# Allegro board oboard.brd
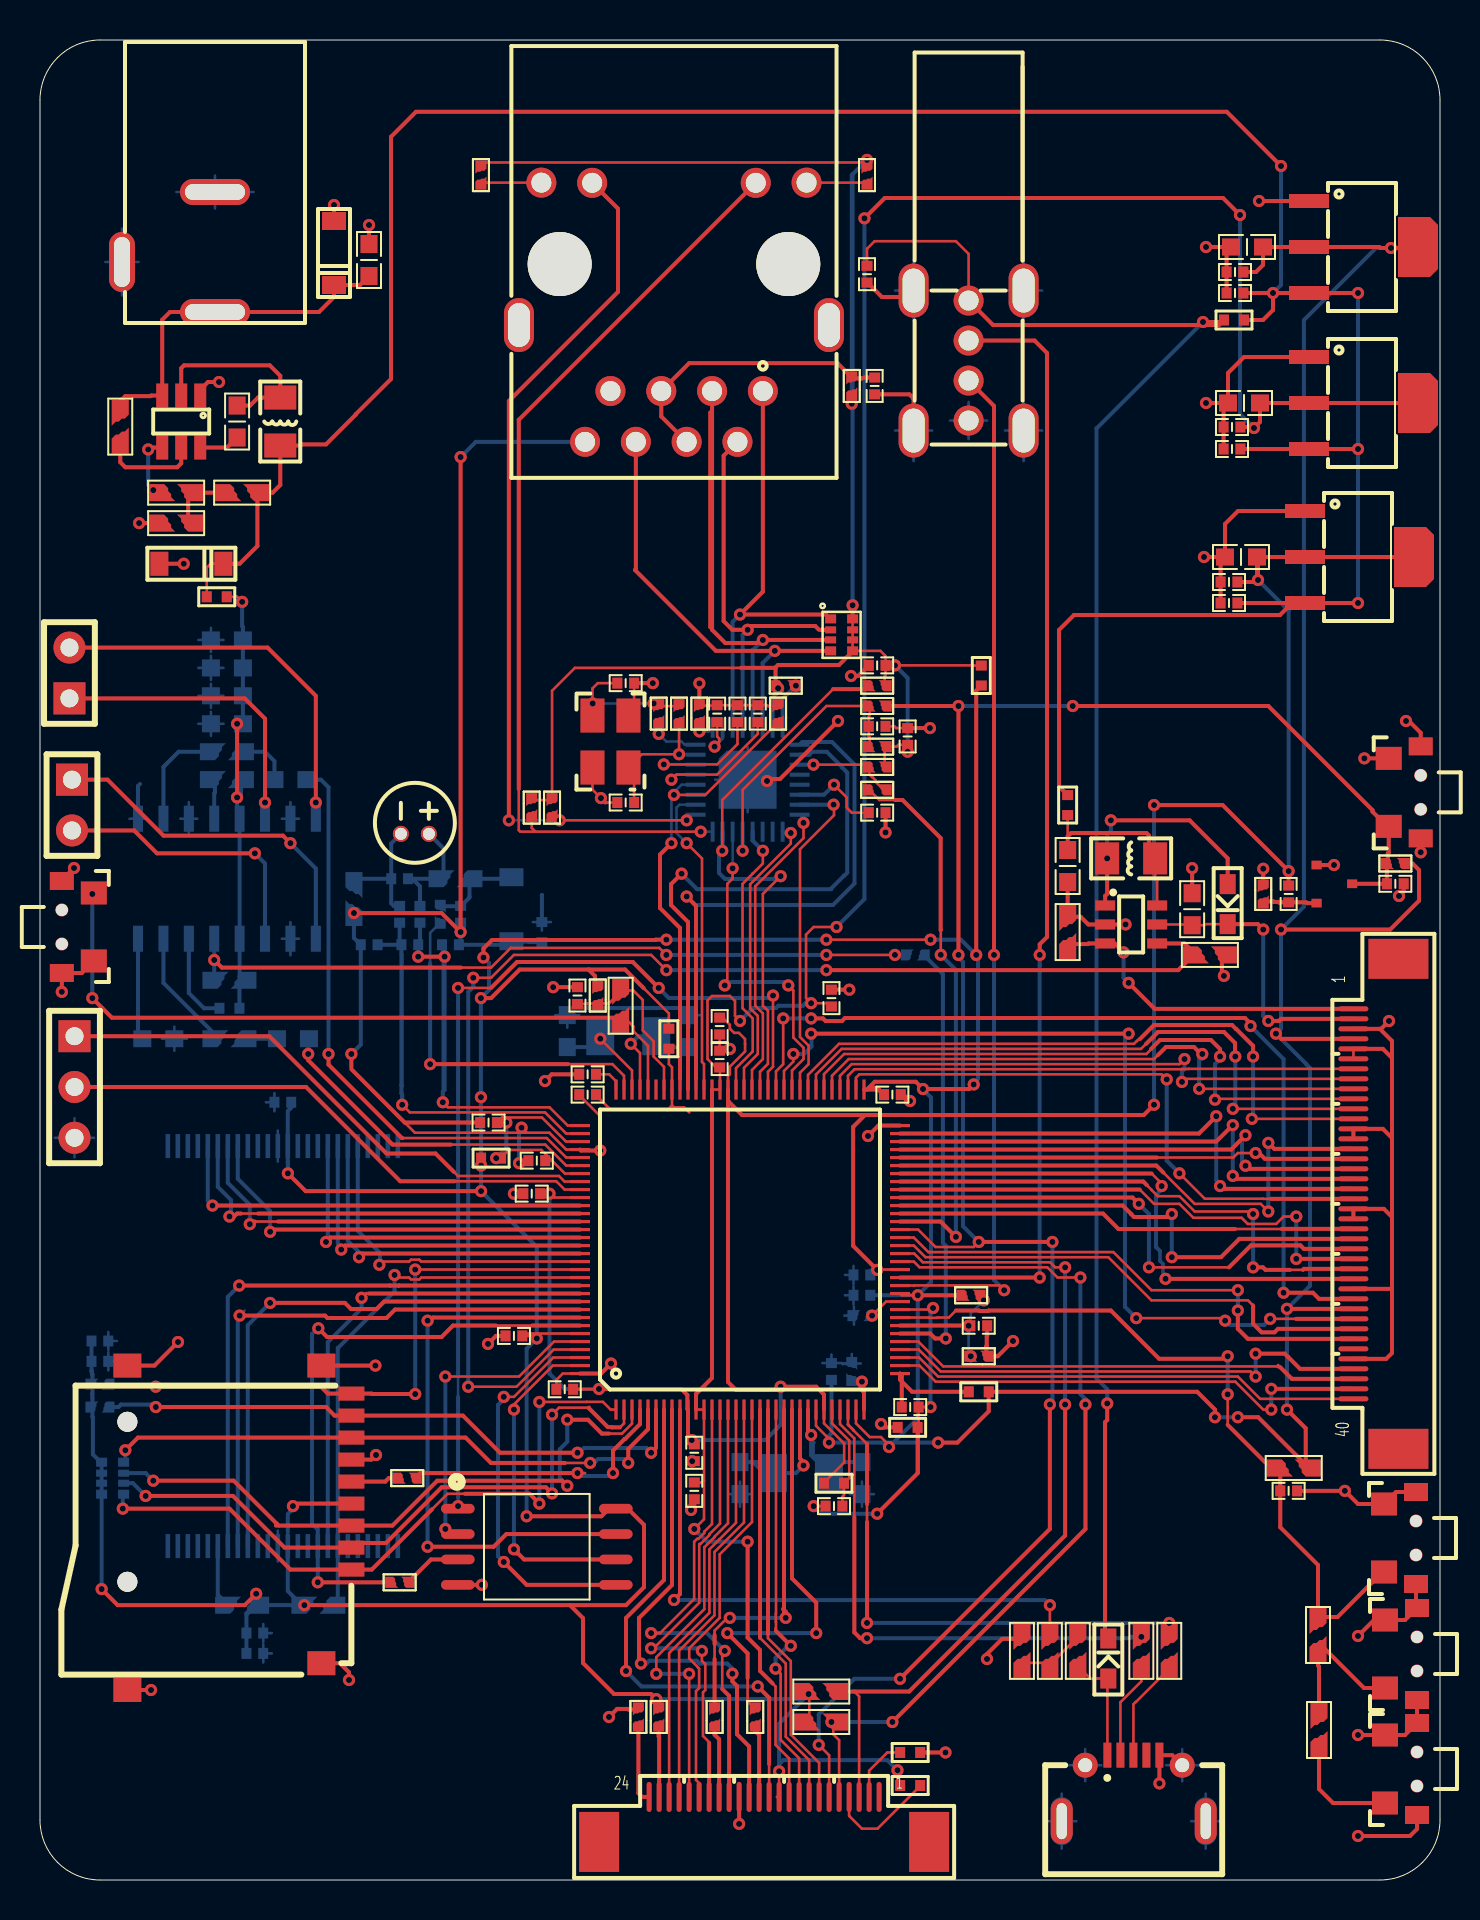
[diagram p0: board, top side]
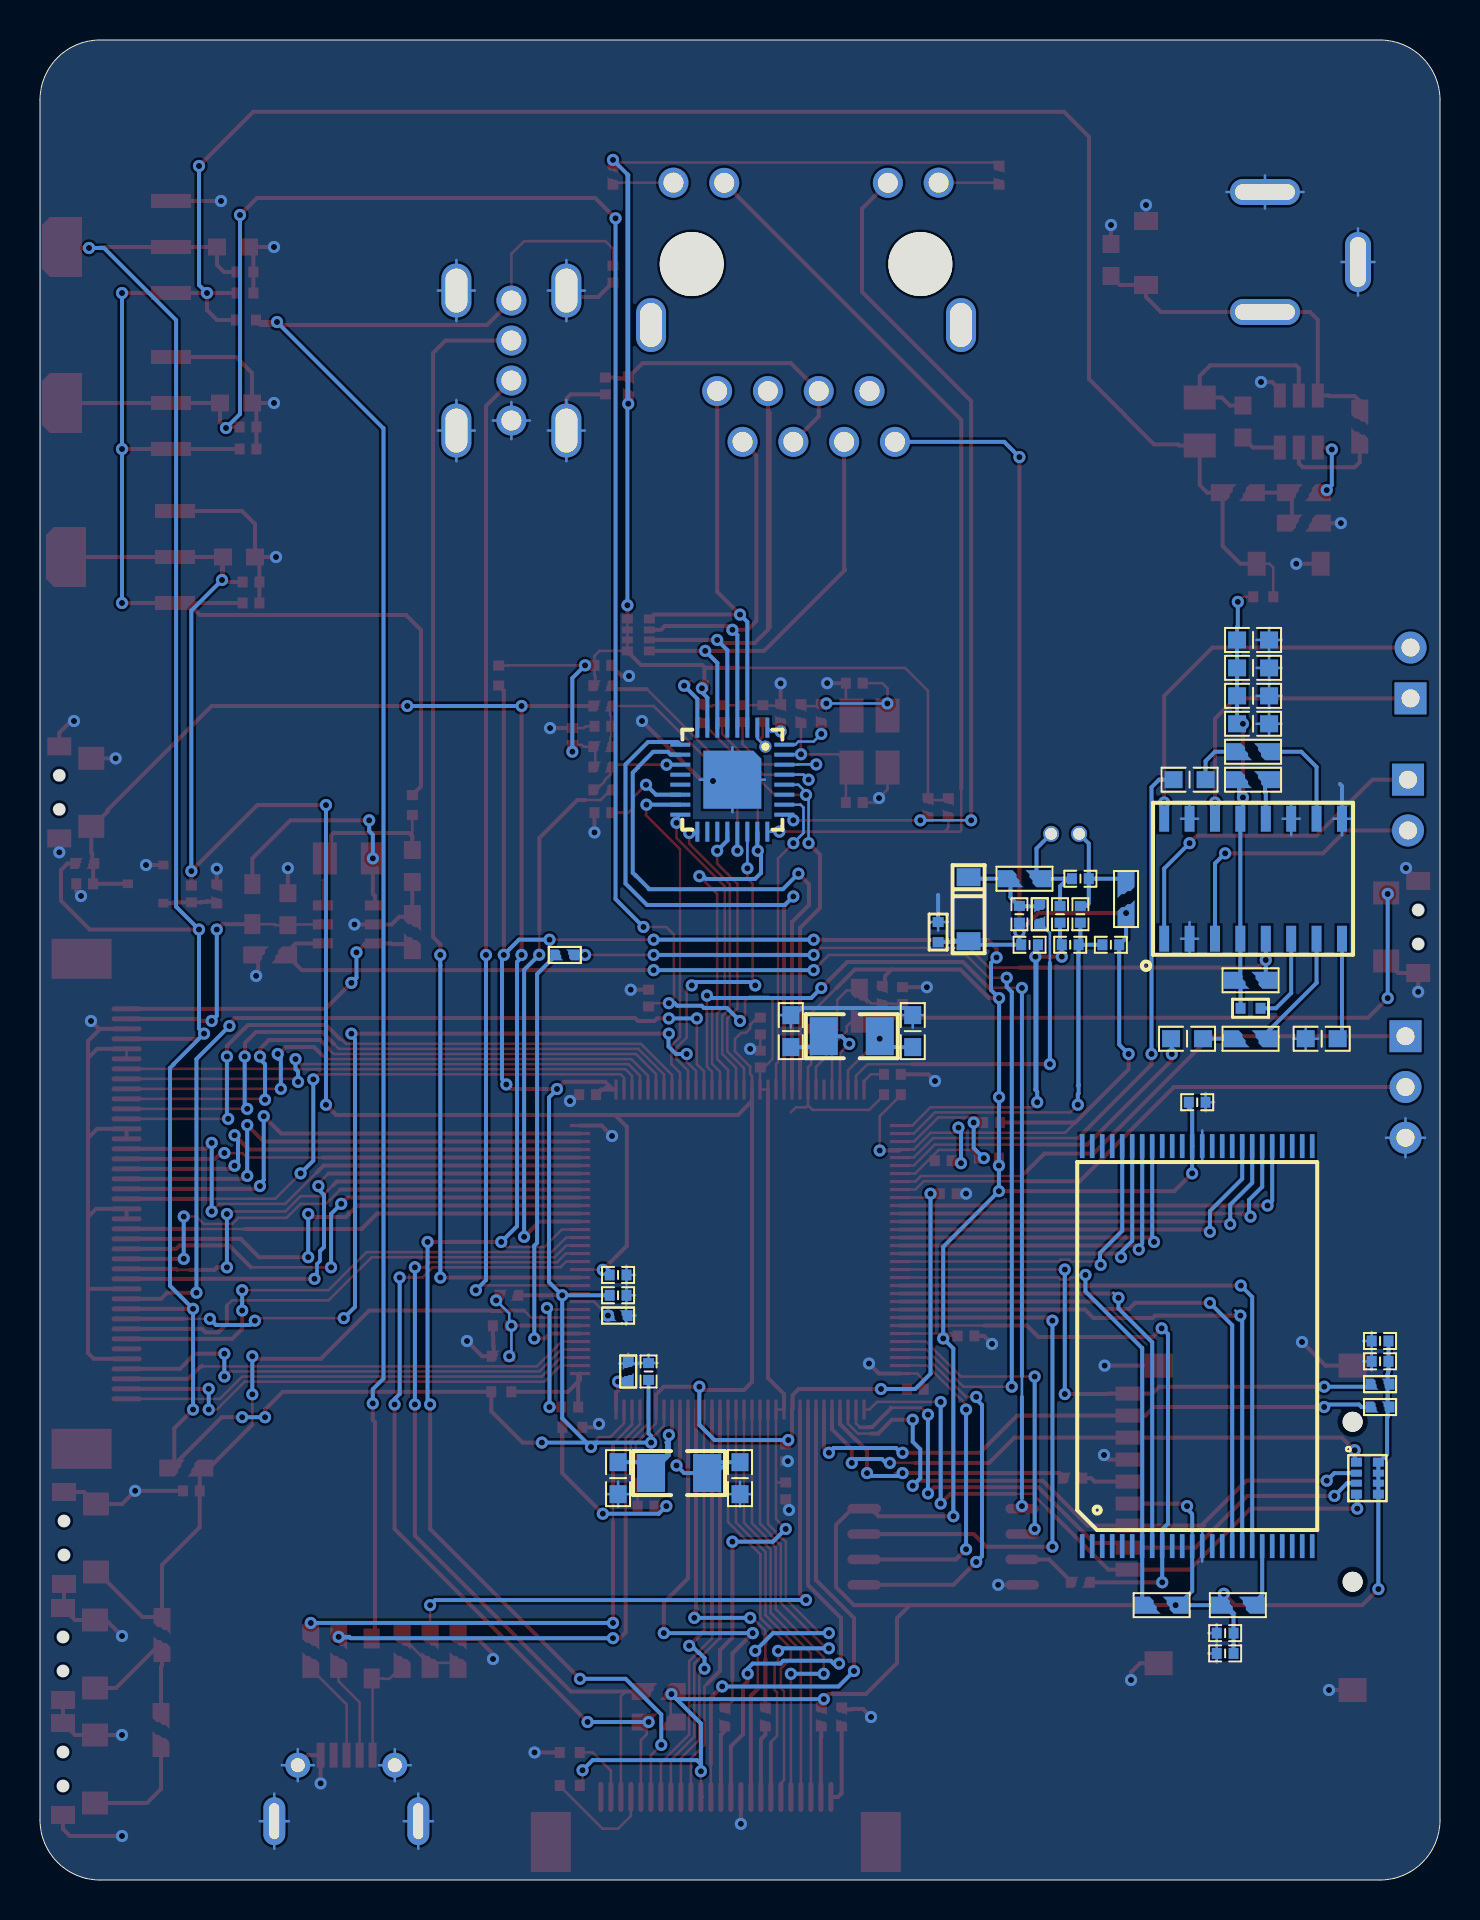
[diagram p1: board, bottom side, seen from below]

Outline 70 x 92 mm; copper layers: TOP, BOTTOM. Coordinates in mm from the lower left corner of the outline.
Outline path: 0,89 0,3 arc(0.88,0.88) 3,0 67,0 arc(69.12,0.88) 70,3 70,89 arc(69.12,91.12) 67,92 3,92 arc(0.88,91.12) 0,89

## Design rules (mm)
constraint set DEFAULT: min track width 0.127

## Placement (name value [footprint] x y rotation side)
C1  1uF  [CAP0402]  27.38 40.28 180 top
C2  15pF  [CAP0603]  32.46 42.44 90 bottom
C3  15pF  [CAP0603]  26.36 42.44 90 bottom
C4  15pF  [CAP0603]  41.1 20.09 270 bottom
C5  15pF  [CAP0603]  35 20.09 270 bottom
C6  0.1uF  [CAP0402]  46.94 27.71 0 top
C7  100nF  [CAP0402]  26.87 44.22 90 top
C8  100nF  [CAP0402]  33.98 42.7 270 top
C9  100nF  [CAP0402]  22.43 37.87 180 top
C10  100nF  [CAP0402]  41.1 29.24 180 bottom
C11  100nF  [CAP0402]  41.1 30.25 180 bottom
C12  0.1uF  [CAP0402]  62.43 49.3 270 top
C13  100nF  [CAP0402]  24.84 35.97 180 top
C14  100nF  [CAP0402]  42.62 39.27 0 top
C15  100nF  [CAP0402]  26.24 24.54 180 top
C16  0.1uF  [CAP0402]  67.77 49.81 0 top
C17  100nF  [CAP0402]  27.38 39.27 180 top
C18  100nF  [CAP0402]  10.74 11.33 0 bottom
C19  100nF  [CAP0402]  32.71 21.36 270 top
C20  100nF  [CAP0402]  43.51 23.65 0 top
C21  100nF  [CAP0402]  39.57 25.43 90 bottom
C22  100nF  [CAP0402]  24.59 34.32 180 top
C23  100nF  [CAP0402]  39.7 18.7 180 top
C24  100nF  [CAP0402]  23.7 27.2 180 top
C25  100nF  [CAP0402]  32.71 19.46 270 top
C26  100nF  [CAP0402]  33.98 41.05 90 top
C27  100nF  [CAP0402]  39.57 44.09 90 top
C29  0.01uF  [CAP0402]  10.74 12.34 0 bottom
C30  0.01uF  [CAP0402]  12.14 38.89 180 bottom
C31  0.01uF  [CAP0402]  3 26.95 180 bottom
C32  0.01uF  [CAP0402]  3 25.93 180 bottom
C33  1uF  [CAP0603]  51.38 50.7 270 top
C34  0.22uF  [CAP0603]  57.61 48.54 90 top
C35  10uF  [CAP0603]  9.35 60.61 180 bottom
C36  1uF  [CAP0603]  9.35 62 180 bottom
C37  10uF  [CAP0603]  9.35 57.81 180 bottom
C38  1uF  [CAP0603]  9.35 59.21 180 bottom
C39  104  [CAP0402]  62.43 19.46 0 top
C40  220nF  [CAP0603]  12.65 42.06 180 bottom
C41  220nF  [CAP0603]  12.52 55.02 0 bottom
C42  1uF  [CAP0603]  5.92 42.06 180 bottom
C43  2.2uF  [CAP3216]  23.57 48.54 270 bottom
C44  100nF  [CAP0402]  21.03 48.29 270 bottom
C45  2.2uF  [CAP0402]  19 48.29 270 bottom
C46  470pF  [CAP0402]  18.49 46.76 0 bottom
C47  330pF  [CAP0402]  17.98 50.06 0 bottom
C48  2.2uF  [CAP0402]  17.98 48.29 270 bottom
C49  330pF  [CAP0402]  20.52 46.76 0 bottom
C50  330pF  [CAP0402]  16.46 46.76 180 bottom
C51  100nF  [CAP0402]  43.38 57.18 90 top
C52  100nF  [CAP0402]  35.89 58.32 270 top
C53  100nF  [CAP0402]  34.87 58.32 90 top
C54  100nF  [CAP0402]  41.86 60.73 180 top
C55  100nF  [CAP0402]  33.86 58.32 270 top
C56  100nF  [CAP0402]  41.86 53.37 0 top
C57  100nF  [CAP0402]  41.73 74.7 270 top
C58  20pF  [CAP0402]  29.29 53.87 0 top
C59  100nF  [CAP0402]  41.86 57.68 0 top
C60  20pF  [CAP0402]  29.29 59.84 180 top
C61  100nF  [CAP0402]  59.75 79.35 180 top
C62  2.2uF  [CAP0603]  60.35 81.65 180 top
C63  100nF  [CAP0402]  59.75 80.4 180 top
C64  100nF  [CAP0402]  59.6 71.55 180 top
C65  2.2uF  [CAP0603]  60.2 73.85 180 top
C66  100nF  [CAP0402]  59.6 72.65 180 top
C67  100nF  [CAP0402]  59.45 63.85 180 top
C68  2.2uF  [CAP0603]  60.05 66.15 180 top
C69  100nF  [CAP0402]  59.45 64.9 180 top
C70  1uF  [CAP0603]  9.85 72.92 270 top
C71  22uF  [CAP3216]  7.57 65.81 180 top
C72  6V/22uF  [CAP3216]  14.7 81.35 90 top
C73  6V/0.1uF  [CAP0603]  16.45 81 90 top
C74  0.1uF  [CAP0402]  41.35 80.29 270 top
D1  1N4148  [1N4148-SOD323]  59.38 48.79 90 top
D2  1N4148  [1N4148-SOD323]  53.41 11.08 270 top
J1  -  [TF-SOCKET]  15.57 15.52 270 top
J2  LCD_RGB_40P  [FPC-40]  68.02 33.81 90 top
J3  OV2640_DVP_24P  [FPC-24]  32.21 1.8 0 top
J4  Speaker Left  [HEADER1X2_2_54]  1.6 55.02 0 top
J5  Speaker Right  [HEADER1X2_2_54]  1.47 59.08 180 top
J6  Debug  [HEADER1X3_2_54]  1.73 42.19 0 top
J8  RJ45  [RJ45_13F-64GYDP2NL]  31.7 71.91 180 top
J9  USB  [USB-AF]  46.43 75.97 0 top
J10  USB  [MICROUSB]  54.69 5.74 180 top
J11  DC 005 25A  [DC_005_25A]  8.75 91.9 270 top
L1  BLM15AG102  [BLM15AG221SN1D]  22.55 36.09 0 top
L2  BLM15AG102  [BLM15AG221SN1D]  31.44 42.06 270 top
L3  22uH  [MLF2012]  54.56 51.08 180 top
L4  10uH  [BLM15AG221SN1D]  9.47 43.59 180 bottom
L5  BLM15AG102  [BLM15AG221SN1D]  47.06 60.22 90 top
L6  4.7uH  [MLF2012]  12.01 72.92 270 top
L7  BLM15AG102  [BLM15AG221SN1D]  8.84 64.16 180 top
L8  BLM15AG102  [BLM15AG221SN1D]  46.94 24.41 0 top
L9  BLM15AG102  [BLM15AG221SN1D]  39.7 19.84 180 top
L10  BLM15AG102  [BLM15AG221SN1D]  25.09 47.4 90 bottom
L11  BLM15AG102  [BLM15AG221SN1D]  59.7 78 180 top
L12  BLM15AG102  [BLM15AG221SN1D]  51.38 53.75 270 top
L13  BLM15AG102  [BLM15AG221SN1D]  43.51 4.73 180 top
L14  BLM15AG102  [BLM15AG221SN1D]  43.51 6.38 0 top
L15  BLM15AG102  [BLM15AG221SN1D]  43.38 22.63 180 top
Q1  SS8050  [SOT23]  64.72 49.81 0 top
R1  12.1K 1%  [RES0402]  40.59 25.43 90 bottom
R2  12.1K 1%  [RES0402]  41.1 28.22 180 bottom
R3  0R  [RES0402]  27.89 44.22 270 top
R4  100K  [RES0603]  29.03 43.71 270 top
R5  1K/DNP  [RES0402]  46.56 29.24 0 top
R6  10K/DNP  [RES0402]  46.94 26.19 0 top
R7  100K  [RES0402]  67.77 50.83 0 top
R8  10K  [RES0402]  61.16 49.3 90 top
R9  100K  [RES0603]  13.92 13.74 0 bottom
R10  100K  [RES0603]  10.11 13.74 180 bottom
R11  0R  [RES0402]  17.98 14.89 0 top
R12  100K  [RES0402]  3 23.65 180 bottom
R13  100K  [RES0402]  3 24.79 180 bottom
R14  22R  [RES0402]  18.36 20.09 180 top
R15  22R  [RES0402]  35.76 8.15 270 top
R16  22R  [RES0402]  33.73 8.15 270 top
R17  0R/DNP  [RES0402]  30.94 8.15 270 top
R18  0R/DNP  [RES0402]  29.92 8.15 270 top
R19  10K  [RES0603]  39.06 7.9 0 top
R20  10K  [RES0603]  39.06 9.42 0 top
R21  5R1  [RES0603]  51.38 47.4 90 top
R22  100K  [RES0603]  58.5 46.25 0 top
R23  100K  [RES0603]  62.69 20.6 0 top
R24  10K  [RES0603]  9.35 55.02 0 bottom
R25  10K  [RES0603]  63.9 12.25 270 top
R26  10K  [RES0603]  63.95 7.5 270 top
R28  10K  [RES0603]  9.47 42.06 180 bottom
R29  10K  [RES0603]  9.35 56.41 0 bottom
R30  10K  [RES0603]  9.47 44.98 180 bottom
R31  0R  [RES0402]  43.76 46.25 180 bottom
R32  0R  [RES0402]  20.01 48.29 90 bottom
R33  1.5K  [RES0603]  20.78 50.06 180 bottom
R34  5.1K  [RES0603]  15.7 49.05 90 bottom
R35  0R  [RES0402]  40.59 74.7 270 top
R36  0R  [RES0402]  41.86 54.51 0 top
R37  0R  [RES0402]  41.86 58.7 180 top
R38  10K  [RES0402]  41.86 56.67 180 top
R39  0R  [RES0402]  32.97 58.32 270 top
R40  1M  [RES0402]  31.95 58.32 90 top
R41  0R  [RES0402]  30.94 58.32 90 top
R42  4.7K  [RES0402]  37.29 59.72 180 top
R43  4.7K  [RES0402]  41.86 55.65 0 top
R44  4.7K  [RES0402]  41.86 59.72 0 top
R45  4.7K  [RES0402]  25.6 53.62 90 top
R46  330R  [RES0402]  22.05 85.24 90 top
R47  4.7K  [RES0402]  24.59 53.62 90 top
R48  330R  [RES0402]  41.35 85.24 90 top
R49  4.7K  [RES0402]  36.91 58.32 270 top
R50  100K  [RES0603]  4.01 72.67 270 top
R51  40.2K  [RES0603]  10.11 69.37 180 top
R52  75K  [RES0603]  6.81 69.37 0 top
R53  13K  [RES0603]  6.81 67.84 0 top
R54  22R  [RES0603]  55.07 11.46 90 top
R55  22R  [RES0603]  56.46 11.46 90 top
R56  10K  [RES0603]  50.49 11.46 90 top
R57  10K  [RES0603]  51.89 11.46 90 top
R58  22K  [RES0603]  49.1 11.46 90 top
RN1  10K 0402 RESAR  [RN4D02_0402]  3.63 20.09 270 bottom
RN2  49.9R 0402 RESAR  [RN4D02_0402]  40.08 62.26 270 top
SW1  TS_018-4.55x3.5x1.8  [TS_018-4P55X3P5X1P8]  1.09 47.65 180 top
SW2  TS_018-4.55x3.5x1.8  [TS_018-4P55X3P5X1P8]  69.04 54.38 0 top
SW3  TS_018-4.55x3.5x1.8  [TS_018-4P55X3P5X1P8]  68.8 17.1 0 top
SW4  TS_018-4.55x3.5x1.8  [TS_018-4P55X3P5X1P8]  68.85 11.3 0 top
SW5  TS_018-4.55x3.5x1.8  [TS_018-4P55X3P5X1P8]  68.85 5.55 0 top
U1  N3292xUxDN  [N3292XUXDN-LQFP128]  35 31.52 90 top
U2  W29N01  [W290XHVSINA-TSOP48]  12.14 26.7 90 bottom
U3  W25QXX  [W25QXX_SOP8_208MIL]  24.84 16.66 0 top
U4  PT4101  [PT4101-SOT23-6]  54.56 47.78 0 top
U5  PAM8403  [PAM8403-SOP16]  9.35 50.06 90 bottom
U6  MIC  [GMI4015-MIC]  18.74 52.86 270 top
U7  RT8201F-QFN32  [RTL8201-QFN32]  35.38 55.02 270 bottom
U8  AMS1117-SOT223-3-3V3  [AMS1117-SOT223-3]  66.1 81.65 270 top
U9  AMS1117-SOT223-3-1V8  [AMS1117-SOT223-3]  66.1 73.85 270 top
U10  AMS1117-SOT223-3-1V2  [AMS1117-SOT223-3]  65.9 66.15 270 top
U11  MP1470  [MP1470-TSOT23-6]  7.06 72.92 180 top
Y1  32768Hz  [CRYSTAL-3215]  29.41 42.19 180 bottom
Y2  12MHz  [CRYSTAL-3215]  38.05 20.35 180 bottom
Y3  25MHz  [YSX321SL-3_2X2_5X0_8]  28.52 56.92 90 top

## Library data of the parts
C1-C27 C29-C32 C51-C57 C59 C61 C63 C64 C66 C67 C69 C74 = CAP NP
C33-C42 C44 C46 C47 C49 C50 C58 C60 C70-C73 = CAPACITOR NON-POL
C43 C45 C48 C62 C65 C68 = CAP POL
D1 D2 = DIODE
J1 = TF-SOCKET
J2 = LCD_RGB_40P
J3 = OV2640_DVP_24P
J4 J5 = HEADER 2
J6 = HEADER 3
J8 = RJ45
J9 = USB AF
J10 = MICROUSB
J11 = DC005-25A
L1 L2 L5 L7-L15 = INDUCTOR
L3 L4 L6 = INDUCTOR/SM
Q1 = BPW37/TO
R1-R20 R35-R39 R54-R58 = RESISTOR
R21-R26 R28-R34 R40-R53 = RESISTOR/SM
RN1 RN2 = RESAR_IS_4/SM
SW1-SW5 = TS_018-4.55x3.5x1.8
U1 = N3292xUxDN
U2 = W29N01 GVSCAA
U3 = W25QXX
U4 = PT4101
U5 = PAM8403
U6 = MIC
U7 = RT8201F-QFN32
U8-U10 = ASM1117-SOT223-3
U11 = MP1470
Y1 Y2 = CRYSTAL
Y3 = YSX321SL

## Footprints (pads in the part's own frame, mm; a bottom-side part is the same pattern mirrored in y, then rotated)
1N4148-SOD323
  custom 0.2x0.2 smd: 1(-1,0) 2(1,0)
AMS1117-SOT223-3
  custom 0.175x0.175 smd: 1(-2.3,-2.65) 2(0,-2.65) 3(2.3,-2.65)
  custom 0.5x0.5 smd: 4(0,2.8)
BLM15AG221SN1D
  custom 0.125x0.125 smd: 1(-0.5,0) 2(0.5,0)
CAP0402
  custom 0.125x0.125 smd: 1(-0.42,0) 2(0.42,0)
CAP0603
  custom 0.212x0.212 smd: 1(-0.8,0) 2(0.8,0)
CAP3216
  custom 0.225x0.225 smd: 1(-1.6,0) 2(1.6,0)
CRYSTAL-3215
  custom 0.35x0.35 smd: 1(-1.4,0) 2(1.4,0)
DC_005_25A
  oval 1.3x3.5 hole 0.8x3: 1(13.5,0) 2(7.5,0)
  oval 3x1.3 hole 2.5x0.8: 3(11,-4.65)
FPC-24
  rect 2x3 smd: (-4.25,0.1) (12.25,0.1)
  oval 0.25x1.5 smd: 1(9.75,2.35) 2(9.25,2.35) 3(8.75,2.35) 4(8.25,2.35) 5(7.75,2.35) 6(7.25,2.35) 7(6.75,2.35) 8(6.25,2.35) 9(5.75,2.35) 10(5.25,2.35) 11(4.75,2.35) 12(4.25,2.35) 13(3.75,2.35) 14(3.25,2.35) 15(2.75,2.35) 16(2.25,2.35) 17(1.75,2.35) 18(1.25,2.35) 19(0.75,2.35) 20(0.25,2.35) 21(-0.25,2.35) 22(-0.75,2.35) 23(-1.25,2.35) 24(-1.75,2.35)
FPC-40
  rect 2x3 smd: (-12.25,0.1) (12.25,0.1)
  oval 0.25x1.5 smd: 1(9.75,2.35) 2(9.25,2.35) 3(8.75,2.35) 4(8.25,2.35) 5(7.75,2.35) 6(7.25,2.35) 7(6.75,2.35) 8(6.25,2.35) 9(5.75,2.35) 10(5.25,2.35) 11(4.75,2.35) 12(4.25,2.35) 13(3.75,2.35) 14(3.25,2.35) 15(2.75,2.35) 16(2.25,2.35) 17(1.75,2.35) 18(1.25,2.35) 19(0.75,2.35) 20(0.25,2.35) 21(-0.25,2.35) 22(-0.75,2.35) 23(-1.25,2.35) 24(-1.75,2.35) 25(-2.25,2.35) 26(-2.75,2.35) 27(-3.25,2.35) 28(-3.75,2.35) 29(-4.25,2.35) 30(-4.75,2.35) 31(-5.25,2.35) 32(-5.75,2.35) 33(-6.25,2.35) 34(-6.75,2.35) 35(-7.25,2.35) 36(-7.75,2.35) 37(-8.25,2.35) 38(-8.75,2.35) 39(-9.25,2.35) 40(-9.75,2.35)
GMI4015-MIC
  round 0.8 hole 0.6: 1(0.55,0.7) 2(0.55,-0.7)
HEADER1X2_2_54
  rect 1.6x1.6 hole 0.9: 1(0,0)
  round 1.6 hole 0.9: 2(0,-2.54)
HEADER1X3_2_54
  rect 1.6x1.6 hole 0.9: 1(0,0)
  round 1.6 hole 0.9: 2(0,-2.54) 3(0,-5.08)
MICROUSB
  rect 0.4x1.25 smd: 1(1.315,-0.5) 2(0.665,-0.5) 3(0.015,-0.5) 4(-0.635,-0.5) 5(-1.285,-0.5)
  round 1.25 hole 0.7: 6(-2.425,0) 7(2.425,0)
  oval 1.1x2.3 hole 0.5x1.8: 8(-3.6,2.8) 9(3.6,2.8)
MLF2012
  custom 0.3x0.3 smd: 1(-1.2,0) 2(1.2,0)
MP1470-TSOT23-6
  custom 0.15x0.15 smd: 1(-0.95,-1.3) 2(0,-1.3) 3(0.95,-1.3) 4(0.95,1.3) 5(0,1.3) 6(-0.95,1.3)
N3292XUXDN-LQFP128
  custom 0.04x0.04 smd: 1(-8,6.2) 2(-8,5.8) 3(-8,5.4) 4(-8,5) 5(-8,4.6) 6(-8,4.2) 7(-8,3.8) 8(-8,3.4) 9(-8,3) 10(-8,2.6) 11(-8,2.2) 12(-8,1.8) 13(-8,1.4) 14(-8,1) 15(-8,0.6) 16(-8,0.2) 17(-8,-0.2) 18(-8,-0.6) 19(-8,-1) 20(-8,-1.4) 21(-8,-1.8) 22(-8,-2.2) 23(-8,-2.6) 24(-8,-3) 25(-8,-3.4) 26(-8,-3.8) 27(-8,-4.2) 28(-8,-4.6) 29(-8,-5) 30(-8,-5.4) 31(-8,-5.8) 32(-8,-6.2) 33(-6.2,-8) 34(-5.8,-8) 35(-5.4,-8) 36(-5,-8) 37(-4.6,-8) 38(-4.2,-8) 39(-3.8,-8) 40(-3.4,-8) 41(-3,-8) 42(-2.6,-8) 43(-2.2,-8) 44(-1.8,-8) 45(-1.4,-8) 46(-1,-8) 47(-0.6,-8) 48(-0.2,-8) 49(0.2,-8) 50(0.6,-8) 51(1,-8) 52(1.4,-8) 53(1.8,-8) 54(2.2,-8) 55(2.6,-8) 56(3,-8) 57(3.4,-8) 58(3.8,-8) 59(4.2,-8) 60(4.6,-8) 61(5,-8) 62(5.4,-8) 63(5.8,-8) 64(6.2,-8) 65(8,-6.2) 66(8,-5.8) 67(8,-5.4) 68(8,-5) 69(8,-4.6) 70(8,-4.2) 71(8,-3.8) 72(8,-3.4) 73(8,-3) 74(8,-2.6) 75(8,-2.2) 76(8,-1.8) 77(8,-1.4) 78(8,-1) 79(8,-0.6) 80(8,-0.2) 81(8,0.2) 82(8,0.6) 83(8,1) 84(8,1.4) 85(8,1.8) 86(8,2.2) 87(8,2.6) 88(8,3) 89(8,3.4) 90(8,3.8) 91(8,4.2) 92(8,4.6) 93(8,5) 94(8,5.4) 95(8,5.8) 96(8,6.2) 97(6.2,8) 98(5.8,8) 99(5.4,8) 100(5,8) 101(4.6,8) 102(4.2,8) 103(3.8,8) 104(3.4,8) 105(3,8) 106(2.6,8) 107(2.2,8) 108(1.8,8) 109(1.4,8) 110(1,8) 111(0.6,8) 112(0.2,8) 113(-0.2,8) 114(-0.6,8) 115(-1,8) 116(-1.4,8) 117(-1.8,8) 118(-2.2,8) 119(-2.6,8) 120(-3,8) 121(-3.4,8) 122(-3.8,8) 123(-4.2,8) 124(-4.6,8) 125(-5,8) 126(-5.4,8) 127(-5.8,8) 128(-6.2,8)
PAM8403-SOP16
  custom 0.125x0.125 smd: 1(-3,4.445) 2(-3,3.175) 3(-3,1.905) 4(-3,0.635) 5(-3,-0.635) 6(-3,-1.905) 7(-3,-3.175) 8(-3,-4.445) 9(3,-4.445) 10(3,-3.175) 11(3,-1.905) 12(3,-0.635) 13(3,0.635) 14(3,1.905) 15(3,3.175) 16(3,4.445)
PT4101-SOT23-6
  custom 0.125x0.125 smd: 1(-1.3,0.95) 2(-1.3,0) 3(-1.3,-0.95) 4(1.3,-0.95) 5(1.3,0) 6(1.3,0.95)
RES0402
  custom 0.138x0.138 smd: 1(-0.4,0) 2(0.4,0)
RES0603
  custom 0.212x0.212 smd: 1(-0.7,0) 2(0.7,0)
RJ45_13F-64GYDP2NL
  round 1.5 hole 1: 1(-4.445,-2.54) 2(-3.175,0) 3(-1.905,-2.54) 4(-0.635,0) 5(0.635,-2.54) 6(1.905,0) 7(3.175,-2.54) 8(4.445,0) 9(-6.63,-12.96) 10(-4.09,-12.95) 11(4.09,-12.95) 12(6.63,-12.96)
  round 3.201 hole 3.2: M1(-5.715,-8.89) M2(5.715,-8.89)
  oval 1.5x2.7 hole 1.1x2.2: M3(-7.75,-5.84) M4(7.75,-5.84)
RN4D02_0402
  rect 0.45x0.55 smd: 1(-0.8,-0.55) 4(0.8,-0.55) 5(0.8,0.55) 8(-0.8,0.55)
  rect 0.35x0.55 smd: 2(-0.25,-0.55) 3(0.25,-0.55) 6(0.25,0.55) 7(-0.25,0.55)
RTL8201-QFN32
  custom 0.05x0.05 smd: 1(-2.6,1.75) 2(-2.6,1.25) 3(-2.6,0.75) 4(-2.6,0.25) 5(-2.6,-0.25) 6(-2.6,-0.75) 7(-2.6,-1.25) 8(-2.6,-1.75) 9(-1.75,-2.6) 10(-1.25,-2.6) 11(-0.75,-2.6) 12(-0.25,-2.6) 13(0.25,-2.6) 14(0.75,-2.6) 15(1.25,-2.6) 16(1.75,-2.6) 17(2.6,-1.75) 18(2.6,-1.25) 19(2.6,-0.75) 20(2.6,-0.25) 21(2.6,0.25) 22(2.6,0.75) 23(2.6,1.25) 24(2.6,1.75) 25(1.75,2.6) 26(1.25,2.6) 27(0.75,2.6) 28(0.25,2.6) 29(-0.25,2.6) 30(-0.75,2.6) 31(-1.25,2.6) 32(-1.75,2.6)
  custom 0.725x0.725 smd: 33(0,0)
SOT23
  rect 0.508x0.432 smd: 1(-0.889,0.94) 2(-0.889,-0.965) 3(0.889,0)
TF-SOCKET
  round 1 hole 1.1 unplated: (-7.39,-11.2) (0.61,-11.2)
  rect 0.7x1.3 smd: 1(0,0) 2(-1.1,0) 3(-2.2,0) 4(-3.3,0) 5(-4.4,0) 6(-5.5,0) 7(-6.6,0) 8(-7.7,0) 9(-8.8,0)
  rect 1.2x1.4 smd: 10(-10.2,-1.5) 11(4.68,-1.5) 12(-10.2,-11.2) 13(6.02,-11.2)
TS_018-4P55X3P5X1P8
  round 0.65 hole 0.6: (0,0.85) (0,-0.85)
  custom 0.225x0.225 smd: 1(0,2.3) 2(0,-2.3)
  custom 0.287x0.287 smd: 3(-1.6,1.7) 4(-1.6,-1.7)
USB-AF
  round 1.5 hole 1: 1(0,3) 2(0,1) 3(0,-1) 4(0,-3)
  oval 1.5x2.7 hole 1.1x2.2: 5(-2.75,3.5) 6(2.75,3.5) 7(-2.75,-3.5) 8(2.75,-3.5)
W25QXX_SOP8_208MIL
  custom 0.12x0.12 smd: 1(-3.95,1.905) 2(-3.95,0.635) 3(-3.95,-0.635) 4(-3.95,-1.905) 5(3.95,-1.905) 6(3.95,-0.635) 7(3.95,0.635) 8(3.95,1.905)
W290XHVSINA-TSOP48
  custom 0.058x0.058 smd: 1(-10,5.75) 2(-10,5.25) 3(-10,4.75) 4(-10,4.25) 5(-10,3.75) 6(-10,3.25) 7(-10,2.75) 8(-10,2.25) 9(-10,1.75) 10(-10,1.25) 11(-10,0.75) 12(-10,0.25) 13(-10,-0.25) 14(-10,-0.75) 15(-10,-1.25) 16(-10,-1.75) 17(-10,-2.25) 18(-10,-2.75) 19(-10,-3.25) 20(-10,-3.75) 21(-10,-4.25) 22(-10,-4.75) 23(-10,-5.25) 24(-10,-5.75) 25(10,-5.75) 26(10,-5.25) 27(10,-4.75) 28(10,-4.25) 29(10,-3.75) 30(10,-3.25) 31(10,-2.75) 32(10,-2.25) 33(10,-1.75) 34(10,-1.25) 35(10,-0.75) 36(10,-0.25) 37(10,0.25) 38(10,0.75) 39(10,1.25) 40(10,1.75) 41(10,2.25) 42(10,2.75) 43(10,3.25) 44(10,3.75) 45(10,4.25) 46(10,4.75) 47(10,5.25) 48(10,5.75)
YSX321SL-3_2X2_5X0_8
  custom 0.3x0.3 smd: 1(-1.3,-0.9) 2(1.3,-0.9) 3(1.3,0.9) 4(-1.3,0.9)

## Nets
AVDD1V2: C23.1 L9.1 U1.28
AVDD3V3: C20.1 L8.1 U1.33
AVDD3V3_AUDIO: C9.1 C13.1 L1.2 U1.99 U1.103
AVDD3V3_TV: C17.1 L2.2 U1.89
AVDD5V: C35.1 C36.1 C37.1 C38.1 L4.1 L7.1 R24.2 R30.1 U5.4 U5.13
DVDD1V2: C8.1 C11.1 C12.1 C15.1 C19.1 C22.1 C68.1 C69.1 L9.2 U1.10 U1.27 U1.46 U1.82 U1.106 U10.2 U10.4(VOUT)
DVDD1V8: C25.1 C26.1 C27.1 C65.1 C66.1 J3.10 U1.11 U1.12 U1.83 U1.84 U9.2 U9.4(VOUT)
DVDD5V: C61.1 C64.1 C67.1 C71.1 L6.2 L7.2 L11.1 L12.1 R51.1 U8.3 U9.3 U10.3
DVDD33: C10.1 C14.1 C18.1 C21.1 C24.1 C29.1 C30.1 C31.2 C32.2 C62.1 C63.1 J1.4(VDD) J2.4 J2.31 J3.11 L1.1 L2.1 L5.1 L8.2 L13.2 R3.1 R5.1 R7.2 R9.1 R10.1 R12.2 R13.2 R17.1 R19.1 R20.1 R23.2 RN1.5 RN1.6 RN1.7 RN1.8 U1.26 U1.31 U1.43 U1.65 U1.123 U2.12 U2.37 U3.8 U8.2 U8.4(VOUT)
GND: C1.2 C2.2 C3.2 C4.2 C5.2 C6.2 C7.2 C8.2 C10.2 C11.2 C14.2 C15.2 C16.2 C18.2 C19.2 C21.2 C22.2 C24.2 C25.2 C26.2 C27.2 C29.2 C30.2 C31.1 C32.1 C33.2 C34.2 C35.2 C36.2 C37.2 C38.2 C39.2 C42.1 C51.2 C52.1 C53.2 C54.2 C55.1 C56.2 C57.2 C58.1 C59.2 C60.1 C61.2 C62.2 C63.2 C64.2 C65.2 C66.2 C67.2 C68.2 C69.2 C71.2 C72.2 C73.2 C74.2 J1.6 J1.10 J1.11 J1.12 J1.13 J2.3 J2.5 J2.6 J2.13 J2.14 J2.21 J2.22 J2.29 J2.36 J3.15 J6.3 J9.4 J9.5 J9.6 J9.7 J9.8 J10.5 J10.6 J10.7 J10.8 J10.9 J11.2(COM) J11.3 L10.2 L14.2 L15.2 Q1.1(EMITTER) R1.2 R2.2 R6.2 R8.2 R18.1 R21.2 R22.2 R39.1 R49.1 R53.1 R58.2 SW1.1 SW1.2 SW1.3 SW2.1 SW2.2 SW2.3 SW3.1 SW3.2 SW3.3 SW4.1 SW4.2 SW4.3 SW5.1 SW5.2 SW5.3 U1.64 U1.128 U2.13 U2.36 U3.4 U4.2 U5.2 U5.9 U5.11 U5.15 U7.33 U8.1 U9.1 U10.1 U11.1 Y3.2 Y3.4
GND_FIELD SIGNAL: C20.2 C23.2 L15.1 U1.41
GND_SIGNAL: C9.2 C13.2 C17.2 C43.2 C44.2 C49.2 C50.2 J8.8 L10.1 R34.1 U1.100
PVIN: C72.1 C73.1 J11.1 R50.1 U11.3
VBUS: C74.1 D2.1(K) J9.1(VBUS) L11.2
ADC_MID: C1.1 U1.96
AHS: C6.1 R5.2 R6.1 U1.39
BL_5V: C33.1 L3.1 L12.2 U4.6
BL_ADJ: R22.1 U1.125 U4.4
DEBUG_RX: J6.2 U1.105
DEBUG_TX: J6.1 U1.104
ETH_CRS: U1.85 U7.26
ETH_INT: R36.1 U1.52
ETH_INT_PU: R36.2 R43.1 U7.11
ETH_LED0+: J8.9 R48.1
ETH_LED0-: J8.10 R47.1 U7.24
ETH_LED1+: J8.12 R46.1
ETH_LED1-: J8.11 R45.1 U7.25
ETH_MDC: U1.74 U7.22
ETH_MDIO: R44.1 U1.78 U7.23
ETH_REFCLK: U1.73 U7.15
ETH_RESET: C16.1 J3.6 Q1.3 R7.1 R37.1 SW2.4 U1.51
ETH_RXD0: U1.86 U7.9
ETH_RXD1: U1.87 U7.10
ETH_RXDV: R42.1 U7.8
ETH_RXER: R49.2 U1.88 U7.28
ETH_TXD0: U1.79 U7.16
ETH_TXD1: U1.80 U7.17
ETH_TXEN: U1.81 U7.20(TXEN)
ETH_VCCD: C51.1 C54.1 L5.2 R35.2 R38.1 R42.2 R43.2 R44.2 R45.2 R46.2 R47.2 R48.2 RN2.5 RN2.6 RN2.7 RN2.8 U7.7
GPG7: R31.1 U1.38
HPOUTL: C40.1 U1.102
HPOUTR: C41.2 U1.101
ISI_HSYNC: J3.9 U1.21
ISI_PCLK: R16.1 U1.22
ISI_PWDN: J3.8 U1.19
ISI_SCL: J3.5 R19.2 U1.47
ISI_SCLK: R15.1 U1.23
ISI_SDA: J3.3 R20.2 U1.48
ISI_VSYNC: J3.7 U1.20
LED+: C34.1 D1.1(K) J2.2 U4.5
LED-: J2.1 R21.1 U4.3
LHSYNC: J2.32 U1.75
LPCLK: J2.30 U1.76
LRADC: C39.1 R23.1 R25.1 SW3.4 U1.40
LVD0: J2.23 U1.53
LVD1: J2.24 U1.54
LVD2: J2.25 U1.55
LVD3: J2.26 U1.56
LVD4: J2.27 U1.57
LVD5: J2.28 U1.58
LVD6: J2.15 U1.59
LVD7: J2.16 U1.60
LVD8: J2.17 U1.61
LVD9: J2.18 U1.62
LVD10: J2.19 U1.63
LVD11: J2.20 U1.66
LVD12: J2.7 U1.67
LVD13: J2.8 U1.68
LVD14: J2.9 U1.69
LVD15: J2.10 U1.70
LVD16: J2.11 U1.71
LVD17: J2.12 U1.72
LVDE: J2.34 U1.50
LVSYNC: J2.33 U1.49
MIC_BIAS: R32.1 U1.95
MIC_INN: C46.1 C48.2 C50.1 U1.98
MIC_INP: C45.2 C46.2 C49.1 U1.97
MUTE: R30.2 R31.2 U5.5
NALE: U1.120 U2.17
NBUSY0: R9.2 U1.116 U2.7
NCLE: U1.119 U2.16
NCS0: R11.1 U1.122 U2.9
NCS1: U1.121 U3.7
ND0: U1.107 U2.29
ND1: U1.108 U2.30
ND2: U1.109 U2.31
ND3: U1.110 U2.32
ND4: U1.111 U2.41
ND5: U1.112 U2.42
ND6: U1.113 U2.43
ND7: U1.114 U2.44
NRE: U1.118 U2.8
NWR: U1.117 U2.18
OUTLM: J4.2 U5.3
OUTLP: J4.1 U5.1
OUTRM: J5.1 U5.14
OUTRP: J5.2 U5.16
RTC_XIN: C2.1 U1.93 Y1.1
RTC_XOUT: C3.1 U1.94 Y1.2
RTCVDD33: C7.1 R3.2 R4.1 U1.90
SD_CD: J1.9 R13.1 U1.115
SD_CLK: R14.1 U1.4
SD_CMD: J1.3 RN1.2 U1.3
SD_D0: J1.7 RN1.1 U1.5
SD_D1: J1.8 R12.1 U1.6
SD_D2: J1.1 RN1.4 U1.1
SD_D3: J1.2 RN1.3 U1.2
SF_CLK: U1.127 U3.6
SF_CS: U1.77 U3.1
SF_DI: U1.126 U3.5
SF_DO: U1.124 U3.2
SPD0: J3.19 U1.18
SPD1: J3.21 U1.17
SPD2: J3.22 U1.16
SPD3: J3.20 U1.15
SPD4: J3.18 U1.14
SPD5: J3.16 U1.13
SPD6: J3.14 U1.8
SPD7: J3.12(Y9) U1.7
TP_XM: J2.39 U1.34
TP_XP: J2.37 U1.36
TP_YM: J2.40(YU) U1.35
TP_YP: J2.38 U1.37
UD_REXT: R1.1 U1.32
UH_DM: J9.2 U1.45
UH_DP: J9.3 U1.44
UH_REXT: R2.1 U1.42
USB_DET: R56.2 U1.9
USB_DM: R54.2 U1.29
USB_DP: R55.2 U1.30
USB_VIN: D2.2 J10.1(VBUS) R57.1
XIN: C4.1 U1.25 Y2.1
XOUT: C5.1 U1.24(XOUT) Y2.2
N04211: R10.2 U2.19(W\P\)
N06862: J1.5 R14.2
N09654: R11.2 U3.3(W\P\/IO2)
N15646006: J3.13 R15.2
N15646070: J3.17 R16.2
N15663479: C52.2 U7.29
N15663486: C55.2 U7.2
N15663493: C56.1 U7.14
N15663500: C53.1 U7.30
N15663575: C59.1 R37.2 R38.2 U7.21
N15663676: R39.2 U7.1
N15663702: R41.1 U7.32
N15664512: C60.2 R40.2 R41.2 Y3.3(XOUT)
N15664809: C58.2 R40.1 U7.31 Y3.1
N15668493: J8.1 RN2.1 U7.3
N15668513: J8.2(TD-) RN2.2 U7.4
N15668525: J8.3 RN2.3 U7.5
N15668529: J8.6 RN2.4 U7.6
N15668719: C57.1 J8.4 J8.5 R35.1
N15674337: R25.2 R26.1 SW4.4
N15674345: R26.2 SW5.4
N15676008: R24.1 U5.12
N15676062: L4.2 U5.6
N15676114: C40.2 R28.1
N15676138: R28.2 U5.7
N15676142: R29.1 U5.10
N15676150: C41.1 R29.2
N15676164: C42.2 U5.8(VREF)
N15687660: C70.2 U11.6
N15687760: C70.1 L6.1 U11.2(SW)
N15687792: R50.2 U11.5
N15687876: R51.2 R52.2 R53.2
N15687912: R52.1 U11.4
N15691835: D1.2 L3.2 U4.1(SW)
N15705525: C43.1 C44.1 R32.2 R33.1
N15705529: C45.1 C47.2 R33.2 U6.1
N15705631: C47.1 C48.1 R34.2 U6.2(-)
N15714383: J10.2 R54.1
N15714387: J10.3 R55.1
N15739714: R4.2 SW1.4 U1.92
N15742573: C12.2 Q1.2 R8.1
N15750041: R56.1 R57.2 R58.1
N15763803: J3.24 R18.2
N15763807: J3.23 R17.2
N15841040: J3.4 L13.1
N15841559: J3.2 L14.1

Pads without a net: J2 35; J3 1; J8 7 M1 M2 M3 M4; J10 4; U1 91; U2 1 2 3 4 5 6 10 11 14 15 20 21 22 23 24 25 26 27 28 33 34 35 38 39 40 45 46 47 48; U7 12 13 18 19 27

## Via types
v1: diameter 0.61, hole 0.305, TOP to BOTTOM, 347 vias

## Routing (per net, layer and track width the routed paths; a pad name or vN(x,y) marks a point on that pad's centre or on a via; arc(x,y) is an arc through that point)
AVDD1V2: length 5.3
  TOP w0.127: C23.1 40.12,19.16 40.2,19.24 L9.1 40.46,20.1 40.46,21.97 39.6,22.83 U1.28
AVDD3V3: length 5.7
  TOP w0.2: L8.1 43.61,24.41 43,25.02 U1.33 43.09,25.23 C20.1
AVDD3V3_AUDIO: length 12.2
  TOP w0.127: v1(23.32,37.87) C9.1 23.1,38.13 25.09,38.13 26.3,36.92 U1.99 ; L1.2 23.05,36.12 23.44,36.5 25.07,36.5 25.6,35.97 ; 25.6,35.97 26.25,35.32 U1.103 ; 25.6,35.97 C13.1
  BOTTOM w0.2: v1(22.81,36.09) 23.32,36.6 v1(23.32,37.87)
AVDD3V3_TV: length 8.1
  TOP w0.127: 31.6,38.73 U1.89 31.6,40.64 31.44,40.79 L2.2 ; 31.6,38.73 31.7,38.63 32.21,38.63 32.46,38.38 ; 31.6,38.73 31.38,38.51 28.54,38.51 27.8,39.24 C17.1
AVDD5V: length 22.7
  TOP w0.127: L7.1 9.85,64.16 v1(10.11,63.91)
  TOP w0.2: v1(9.85,57.81) v1(9.85,54.13)
  BOTTOM w0.127: C37.1 v1(9.85,57.81)
  BOTTOM w0.2: v1(10.11,63.91) 10.11,62.69 10.15,62.65 C36.1 C35.1 C38.1 C37.1 ; R24.2 10.05,54.32 v1(9.85,54.13) 9.85,53.19 U5.13 U5.4 9.98,45.18 R30.1 9.97,44.78 L4.1
DVDD1V2: length 145
  TOP w0.127: U1.27 39.2,22.83 40.21,21.82 40.21,20.87 39.2,19.86 L9.2 ; U1.106 25.73,34.12 25.54,34.32 v1(25.48,34.32) C22.1 ; U1.46 41.87,30.52 v1(41.86,30.51) ; 32.08,24.54 C15.1 ; U1.82 34.4,40.19 34.49,40.28 34.49,40.67 35.25,41.43 35.25,41.81 35.25,41.81 35.25,42.05 34.94,42.36 34.71,42.36 34.49,42.57 34.49,42.76 34.13,43.12 C8.1
  TOP w0.2: C68.1 60.85,65.1 60.65,64.9 C69.1 ; C68.1 U10.2 U10.4 ; C68.1 60.9,66.1 v1(60.9,65) ; v1(55.7,38.76) 55.19,38.25 41.25,38.25 ; C12.1 v1(62.43,50.45) 59.13,53.75 v1(55.7,53.75) ; 41.25,38.25 40.66,37.66 40.66,31.71 v1(41.86,30.51) ; 41.25,38.25 35.1,38.25 34.45,38.9 34.4,38.9 ; 34.4,38.9 U1.82 ; 34.4,38.9 34.4,24.9 34.8,24.5 36.87,24.5 v1(37.03,24.66) 38.81,24.66 39.2,24.27 U1.27 ; v1(32.59,22) 32.4,22.18 U1.10 32.37,23.55 32.37,24.25 32.07,24.55 v1(27.95,24.55)
  BOTTOM w0.127: 41.52,30.51 v1(41.86,30.51) 41.6,30.25 C11.1
  BOTTOM w0.2: v1(32.59,22) 36.27,22 37.03,22.76 v1(37.03,24.66) ; v1(55.7,38.76) v1(55.7,53.75) ; v1(60.9,65) 62.43,63.47 v1(62.43,50.45) ; v1(27.95,24.55) 26.24,24.55 25.48,25.32 v1(25.48,34.32)
DVDD1V8: length 134.7
  TOP w0.127: 33.2,19.96 U1.12 U1.11 ; 33.2,19.96 33.2,18.04 v1(32.71,17.55) ; 33.2,19.96 33.11,19.88 32.71,19.88 ; C27.1 39.41,43.84 v1(38.56,43.84) 38.3,44.09 38.3,47.27 38.68,47.65 v1(39.83,47.65) ; v1(35,42.95) 34.75,43.2 34.75,43.95 34.5,44.2 33.6,44.2 33.38,43.98 33.38,41.05 33.8,40.63 C26.1 34,40.61 U1.83 U1.84 ; 36.63,9.83 36.78,9.68 36.78,6.76 37.46,6.08 J3.10
  TOP w0.2: U9.4 U9.2 C65.1 61,72.9 60.75,72.65 ; v1(35.38,16.92) 35.38,12.12 36,11.5 36,10.46 36.63,9.83 ; v1(60,83.25) 59.15,84.1 42.24,84.1 v1(41.22,83.08) ; U1.84 33.6,25.1 32.8,24.3 U1.11 ; 60.75,72.65 C66.1 ; 60.75,72.65 v1(60.7,72.6)
  BOTTOM w0.127: 39.83,47.52 v1(39.83,47.65)
  BOTTOM w0.2: v1(41.22,83.08) 41.22,49.05 v1(39.83,47.65) ; v1(35.38,16.92) 33.35,16.92 v1(32.71,17.55) ; v1(60.7,72.6) 60,73.3 v1(60,83.25) ; v1(38.56,43.84) 38.28,43.84 38.15,43.71 36.91,43.71 36.8,43.6 35.65,43.6 v1(35,42.95)
DVDD5V: length 138.5
  TOP w0.127: C71.1 8.53,65.81 8.34,65.62 L7.2
  TOP w0.2: C67.1 62.6,63.85 ; 62.6,63.85 U10.3 v1(65.9,63.85) ; 62.6,63.85 62,63.25 51.7,63.25 50.95,62.5 50.95,54.68 L12.1 ; v1(65.9,79.35) U8.3 v1(61.65,79.35) ; C71.1 9.98,65.81 10.87,66.7 10.87,69.31 R51.1 11.63,69.37 12.01,69.75 L6.2 13.04,71.72 13.1,71.78 14.3,71.78 15.78,73.27 15.78,73.28 17.55,75.05 17.55,87.16 18.8,88.41 59.34,88.41 v1(62.05,85.7) ; v1(61.65,79.35) 61.65,78.5 61.15,78 L11.1 ; v1(61.65,79.35) C61.1 ; C64.1 U9.3 v1(65.9,71.55)
  BOTTOM w0.2: v1(61.65,79.35) 62.05,79.75 v1(62.05,85.7) ; v1(65.9,63.85) v1(65.9,71.55) v1(65.9,79.35)
DVDD33: length 358.5
  TOP w0.127: 60.25,23.14 v1(59.89,23.14) ; v1(30.81,9.04) 30.94,8.92 R17.1 ; L13.2 42.87,4.86 v1(42.87,5.49) ; v1(12.65,18.7) 12.77,18.82 12.9,18.82 ; U1.43 43.09,29.24 v1(43.89,29.24) ; v1(36.96,5.44) J3.11 36.84,4.15 ; R19.1 38.46,8 38.46,9.32 R20.1 ; U1.123 24.23,27.32 C24.1 24.71,27.2 v1(24.84,27.08) ; 41.48,39.65 41.73,39.65 42.11,39.27 C14.1 ; U1.26 38.8,22.71 39.45,22.06 v1(39.45,21.87) ; v1(42.45,21.65) 42.45,21.75 42.05,22.15 41.49,22.15 40.8,22.83 U1.31 ; L2.1 31.44,43.33 30.19,44.59 ; v1(39.32,47.02) v1(44.52,47.02) ; 22.58,44.12 22.55,44.09 ; L1.1 v1(22.05,35.72)
  TOP w0.2: v1(22.17,46.13) 22.17,46.57 22.6,47 30.77,47 30.79,47.02 v1(31.32,47.02) ; v1(46.81,46.25) 46.81,59.47 L5.1 ; v1(46.68,39.78) 46.46,39.55 v1(44.15,39.55) 43.79,39.91 41.74,39.91 41.35,39.52 ; 22.55,44.09 v1(22.05,44.09) ; 22.58,44.12 23.98,45.52 27.43,45.52 ; v1(24.33,18.19) 28.07,18.19 28.45,18.57 U3.8 29.39,18.57 30.2,17.76 30.2,14.64 29.3,13.74 26.5,13.74 ; 41.35,39.52 41.95,39.52 C14.1 ; 41.35,39.52 U1.65 ; 60.25,23.14 60.91,23.14 63.39,20.66 R23.2 63.29,20.7 63.29,22.58 v1(62.35,23.52) ; 30.19,44.59 29.25,45.52 27.43,45.52 ; v1(30.81,9.04) 30.55,9.3 28.7,9.3 27.15,10.85 27.15,13.09 26.5,13.74 ; J2.4 62.06,42.06 v1(61.8,42.32) ; v1(43.89,29.24) R5.1 ; U8.4 68.85,81.6 v1(67.55,81.6) 67.02,81.6 66.97,81.65 U8.2 C62.1 61.15,80.75 60.8,80.4 C63.1 ; R3.1 27.75,44.76 27.75,45.2 27.43,45.52 ; v1(12.39,35.33) 13.28,34.44 v1(22.05,34.44) ; 26.5,13.74 v1(13.22,13.74) ; v1(58.75,23.14) 58.75,23.52 57.86,24.41 L8.2 47.44,23.44 45.87,21.87 v1(44.91,21.87) ; R7.2 68.62,50.83 68.95,50.5 68.95,48.96 67.51,47.52 v1(62.05,47.52) ; v1(10.81,14.31) 10.24,13.74 3.89,13.74 v1(3.08,14.55) ; J2.31 v1(62.35,28.56) ; J1.4 12.9,18.82
  BOTTOM w0.127: 22.05,38.64 22.05,38.63 22.05,38.6 ; 12.39,35.87 12.39,35.9 12.39,35.91 ; R10.1 v1(10.81,14.31) ; 2.6,25.41 2.6,25.45 2.58,25.47 ; 12.39,17.4 U2.12 ; 12.39,18.3 12.39,18.2 ; 2.62,25.26 2.6,25.28 2.6,25.32 ; 2.62,24.11 2.6,24.14 2.6,24.3 2.62,24.33 ; 12.39,38.39 12.39,38.45
  BOTTOM w0.2: C21.1 39.57,22.33 39.45,22.2 v1(39.45,21.87) 42.15,21.87 ; v1(44.52,47.02) 46.05,47.02 v1(46.81,46.25) 46.9,46.16 46.9,40.05 46.68,39.83 v1(46.68,39.78) ; v1(24.33,18.19) 24.33,26.57 v1(24.84,27.08) 24.84,31.66 v1(22.05,34.44) v1(22.05,35.72) 22.05,38.6 22.05,38.61 v1(22.05,39.14) v1(22.05,44.09) 22.45,44.5 22.45,45.85 v1(22.17,46.13) ; 12.39,18.3 12.65,18.56 v1(12.65,18.7) ; C30.1 12.56,38.62 12.39,38.45 ; 42.15,21.87 42.37,21.65 v1(42.45,21.65) 43.89,23.09 v1(43.89,29.24) ; 42.15,21.87 v1(44.91,21.87) ; v1(67.55,81.6) 66.8,81.6 63.19,77.99 63.19,48.67 v1(62.05,47.52) 62.05,42.57 v1(61.8,42.32) 63.32,40.79 63.32,40.78 63.5,40.6 63.5,29.71 v1(62.35,28.56) v1(62.35,23.52) ; v1(36.96,5.44) 36.96,5.79 ; 36.96,5.79 37.16,5.99 42.37,5.99 v1(42.87,5.49) ; 36.96,5.79 36.96,7.82 38.17,9.04 ; C31.2 C32.2 2.58,25.43 2.6,25.41 2.6,25.32 2.62,25.29 2.62,24.82 R13.2 2.62,24.77 2.62,23.67 R12.2 2.62,23.62 2.62,23.15 2.65,23.12 2.65,21.28 3.03,20.89 RN1.8 RN1.7 RN1.6 RN1.5 v1(3.08,14.55) ; v1(43.89,29.24) 44.55,29.9 44.55,39.13 44.25,39.43 44.25,39.45 v1(44.15,39.55) ; v1(43.89,29.24) C10.1 ; v1(12.39,35.33) 12.39,35.87 12.39,35.87 U2.37 12.39,38.39 ; 38.17,9.04 v1(38.43,9.3) ; 38.17,9.04 v1(30.81,9.04) ; 10.32,11.33 10.32,13.26 R10.1 13.09,13.74 ; 13.09,13.74 12.39,14.45 U2.12 ; 13.09,13.74 v1(13.22,13.74) ; 12.39,18.2 12.39,17.4 ; v1(31.32,47.02) v1(39.32,47.02) ; v1(58.75,23.14) v1(59.89,23.14)
GND: length 277.3
  TOP w0.127: J2.5 J2.6 ; v1(28.05,54.1) 27.63,54.51 27.63,54.57 27.62,54.58 27.62,55.62 ; C60.1 29.7,58.5 Y3.2 ; C8.2 C26.2 34.4,41.47 v1(34.49,41.55) ; R39.1 33.84,58.72 C55.1 C52.1 36.36,58.74 36.4,58.69 36.88,58.69 R49.1 ; C22.2 v1(23.7,34.32) ; C15.2 25.82,25 26.14,25.32 U1.128 ; C59.2 42.72,57.68 42.81,57.6 C51.2 ; 28.27,53.87 C58.1
  TOP w0.2: J9.7 43.68,74.05 43.65,74.08 43.65,74.1 43.47,74.28 C57.2 ; 2.69,45.95 2.09,45.35 SW1.1 v1(1.09,44.41) ; U11.1 8.01,74.51 8.4,74.9 v1(8.95,74.9) ; C68.2 59.25,67.8 59.9,68.45 U10.1 ; C68.2 59.03,65.93 C69.2 C67.2 ; C68.2 v1(58.2,66.15) ; L15.2 42.22,22.63 v1(42.05,22.8) ; 66.99,42.56 J2.3 ; 66.99,42.56 67.06,42.56 v1(67.45,42.95) ; 66.99,42.56 67.6,41.95 67.6,41.1 ; Q1.1 v1(64.7,50.75) ; v1(65.9,7.25) SW5.3 68.25,7.25 SW5.1 SW4.2 ; v1(28.05,54.1) 28.27,53.87 ; SW5.2 68.85,2.55 68.5,2.2 v1(65.9,2.2) ; C39.2 v1(65.24,19.46) 65.9,18.8 SW3.3 67.8,19.4 SW3.1 ; J1.12 5.72,25.72 v1(6.9,26.9) ; 59.4,81.4 59.4,81.6 59.45,81.65 ; 67.6,29.6 67.6,26.35 67.31,26.06 J2.36 ; 67.6,29.6 67.6,33.15 ; 67.6,29.6 67.56,29.56 J2.29 ; C61.2 C63.2 59.33,81.43 C62.2 59.45,81.65 ; C19.2 v1(32.61,20.94) ; C16.2 68.19,49.44 v1(67.95,49.2) ; 67.6,37.1 67.14,37.56 J2.13 J2.14 ; 67.6,37.1 67.6,33.15 ; 67.6,37.1 67.6,41.1 ; C34.2 v1(57.61,50.59) ; v1(68.3,57.95) 68.44,57.95 69.04,57.36 SW2.1 ; C25.2 32.71,18.66 v1(32.55,18.5) ; SW3.2 68.8,13.65 SW4.1 68.25,13 SW4.3 66.7,13 v1(65.9,12.2) ; 59.45,81.65 v1(58.3,81.65) ; C27.2 v1(40.47,44.52) ; R39.1 v1(32.97,59.83) ; C65.2 59.4,75.35 60.2,76.15 U9.1 ; C65.2 59.18,73.63 C66.2 C64.2 ; C65.2 v1(58.3,73.85) ; C54.2 40.91,60.2 v1(40.55,60.2) ; R22.2 59.09,46.15 59.09,45.3 v1(59.2,45.2) ; v1(43.5,38.95) 43.18,39.27 C14.2 ; 67.6,33.15 67.19,33.56 J2.21 J2.22 ; J10.6 56.61,6.24 J10.5 v1(55.97,4.83) ; C1.2 25.59,40.28 v1(25.25,39.95) ; J1.6 16.57,21.02 v1(16.8,21.25) ; C33.2 R21.2 51.45,48.16 52.03,48.16 52.42,47.78 U4.2 v1(54.28,47.78) ; R53.1 v1(4.96,67.84) ; v1(28.45,8.15) 28.85,8.55 29.39,8.55 29.42,8.53 29.89,8.53 R18.1 ; C73.2 v1(16.45,82.75) ; C72.2 v1(14.7,83.75) ; R8.2 v1(61.16,50.56) ; J2.5 67.14,41.56 67.6,41.1 ; L14.2 v1(45.27,6.38) ; v1(15.45,10) 15.45,10.39 15,10.84 J1.11 ; U3.4 v1(22.09,14.76) ; J1.10 v1(16.77,25.72) ; v1(28.55,25.82) 28.05,25.32 U1.128 ; C71.2 v1(7.19,65.81) ; 1.09,49.95 1.09,49.99 v1(1.7,50.6) ; C51.2 v1(44.5,57.6) ; v1(22.4,26.8) 22.8,27.2 C24.2 ; C56.2 v1(42.28,52.38) ; C7.2 v1(25.66,44.64) ; v1(39.9,57.95) 37,55.05 36.45,55.05 v1(36.35,54.95) ; C74.2 41.38,79.87 42.09,79.15 43.36,79.15 J9.5 ; C60.1 v1(30.64,59.84) ; J1.13 v1(5.55,9.5) ; U8.1 v1(60.95,83.95) ; R58.2 49,12.06 48.11,12.06 47.35,11.3 v1(47.35,11.05) ; SW2.2 v1(69.04,51.39) ; v1(41.4,37.2) 41.92,37.72 U1.64 ; C6.2 47.36,27.21 47.34,27.19 47.34,26.71 47.31,26.69 47.31,26.21 R6.2 47.89,26.19 v1(48.65,26.95) ; J3.15 v1(34.96,2.81) ; SW2.3 v1(66.22,56.08)
  BOTTOM w0.127: 8.55,57.21 C37.2 ; C37.2 9.17,57.81 ; C37.2 8.55,58.41 ; C37.2 7.92,57.81 ; C11.2 40.68,30.7 ; C11.2 40.68,29.8 ; C11.2 40.25,30.25 ; J9.8 49.18,74 ; J9.8 49.18,70.94 ; J9.8 48.25,72.47 ; J9.8 50.11,72.47 ; 43.68,70.94 J9.7 ; J9.7 42.75,72.47 ; J9.7 43.68,74 ; J9.7 44.61,72.47 ; 57.11,4.94 J10.6 ; J10.6 57.11,6.54 ; J10.6 56.31,5.74 ; J10.6 57.91,5.74 ; J10.7 53.06,5.74 ; J10.7 51.46,5.74 ; J10.7 52.26,6.54 ; J10.7 52.26,4.94 ; U5.2 12.95,47.06 ; U5.2 12.09,47.06 ; U5.2 12.52,47.89 ; U5.2 12.52,46.24 ; 7.92,62 C36.2 ; C36.2 8.55,62.61 ; C36.2 8.55,61.4 ; C36.2 9.17,62 ; 32.08,43.46 32.3,43.24 C2.2 ; J11.3 4.1,82.58 ; J11.3 4.1,79.22 ; J11.3 3.27,80.9 ; J11.3 4.93,80.9 ; 24.64,47.9 L10.2 ; L10.2 25.09,47.47 ; L10.2 25.55,47.9 ; C31.1 3.84,26.95 ; C31.1 3.42,26.5 ; C31.1 3.42,27.4 ; C5.2 35,19.92 ; C5.2 34.4,19.29 ; C5.2 35,18.66 ; C5.2 35.6,19.29 ; 45.5,72.97 J9.4 ; J9.4 47.36,72.97 ; J9.4 46.43,72.04 ; J9.4 46.43,73.9 ; 12.09,53.06 U5.15 ; U5.15 12.95,53.06 ; U5.15 12.52,53.89 ; C29.2 11.16,12.8 ; C29.2 11.16,11.89 ; C29.2 11.59,12.34 ; U7.33 35.38,56.64 ; U7.33 35.38,53.39 ; U7.33 33.75,55.02 ; 11.89,15.92 U2.13 11.89,17.47 ; 7.44,52.24 U5.11 ; U5.11 7.44,53.89 ; U5.11 7.01,53.06 ; U5.11 7.87,53.06 ; 40.22,28.22 R2.2 ; R2.2 40.7,28.67 ; R2.2 40.7,27.77 ; C21.2 39.57,26.27 ; C21.2 40.08,25.85 40.12,25.8 40.56,25.8 R1.2 ; C21.2 39.12,25.85 ; 26.36,42.62 C3.2 ; C3.2 26.97,43.24 ; C3.2 25.76,43.24 ; 40.68,28.78 C10.2 ; C10.2 40.68,29.69 ; C10.2 40.25,29.24 ; 37.01,55.02 36.63,55.02 ; R1.2 40.59,26.3 ; R1.2 40.13,25.83 ; R1.2 41.04,25.83 ; C38.2 9.17,59.21 ; C38.2 8.55,59.81 ; C38.2 7.92,59.21 ; C38.2 8.55,58.61 ; C35.2 9.17,60.61 ; C35.2 8.55,61.21 ; C35.2 7.92,60.61 ; C35.2 8.55,60 ; 11.89,37.47 U2.36 11.89,35.92 ; J6.3 1.73,38.09 ; J6.3 2.7,37.11 ; J6.3 1.73,36.13 ; J6.3 0.75,37.11 ; C30.2 11.72,39.34 ; C30.2 11.72,38.44 ; C30.2 11.29,38.89 ; 58.28,1.56 J10.8 ; J10.8 59.01,2.94 ; J10.8 58.28,4.32 ; J10.8 57.56,2.94 ; 6.72,42.06 6.72,42.67 ; 6.72,42.06 6.72,41.46 ; 6.72,42.06 7.34,42.06 ; 6.72,42.06 6.09,42.06 ; C18.2 11.16,11.78 ; C18.2 11.59,11.33 ; C18.2 11.16,10.88 ; 3.42,25.48 C32.1 ; C32.1 3.84,25.93 ; C32.1 3.42,26.39 ; J10.9 51.09,4.32 ; J10.9 50.36,2.94 ; J10.9 51.81,2.94 ; J10.9 51.09,1.56 ; J9.5 43.68,81 ; J9.5 43.68,77.94 ; J9.5 42.75,79.47 ; J9.5 44.61,79.47 ; C4.2 41.1,19.92 ; C4.2 41.7,19.29 ; C4.2 40.49,19.29 ; C4.2 41.1,18.66 ; 4.9,52.24 U5.9 ; U5.9 4.47,53.06 ; U5.9 5.33,53.06 ; 49.18,77.94 J9.6 ; J9.6 49.18,81 ; J9.6 48.25,79.47 ; J9.6 50.11,79.47 ; 6.82,84.4 J11.2 ; J11.2 8.75,83.57 ; J11.2 10.68,84.4 ; J11.2 8.75,85.23 ; 32.46,42.62 C2.2 ; C2.2 33.06,43.24
  BOTTOM w0.2: 5,54.8 4.9,54.7 U5.9 ; 32.08,43.46 31.94,43.6 26.7,43.6 26.36,43.26 C3.2 ; 36.63,55.02 U7.33 ; L10.2 25.09,49.24 25.1,49.25
GND_FIELD SIGNAL: length 19.7
  TOP w0.127: U1.41 44.57,28.52 v1(44.65,28.6) ; v1(44.52,23.65) C20.2 43.93,22.63 ; L15.1 43.93,22.63 ; 43.93,22.63 43.93,20.39 43.88,20.34 ; v1(38.68,18.7) C23.2
  TOP w0.2: v1(41.86,18.31) 43.88,20.34 L15.1
  BOTTOM w0.2: v1(44.65,28.6) 44.52,28.47 v1(44.52,23.65) ; v1(41.86,18.31) 39.06,18.31 v1(38.68,18.7)
GND_SIGNAL: length 73.7
  TOP w0.127: 24.33,37.36 25.47,37.36 26.31,36.52 U1.100 ; 24.33,37.36 v1(24.08,37.62) ; 24.33,37.36 18.74,37.36 18.24,37.87 ; 15.57,40.65 15.57,40.54 ; C17.2 26.96,39.24 28.02,38.19 v1(28.02,36.48) ; C13.2 24.08,35.97 v1(23.95,35.84)
  TOP w0.2: v1(15.57,41.3) 15.57,40.65 ; C9.2 18.24,37.87 15.57,40.54 ; v1(15.7,48.35) 20.08,48.35 v1(21.03,47.4) v1(21.03,71.15) ; U1.100 27.05,36.48 v1(28.02,36.48)
  BOTTOM w0.127: 24.46,46.9 24.45,46.89 24.2,46.89 24.15,46.94
  BOTTOM w0.2: v1(15.57,41.3) 16.04,41.77 C50.2 15.7,47.1 v1(15.7,48.35) ; J8.8 21.79,71.91 v1(21.03,71.15) ; v1(24.08,37.62) 23.95,37.49 v1(23.95,35.84) ; C44.2 v1(21.03,47.4) 21.03,46.85 C49.2 23.39,46.76 C43.2 24.4,46.94 24.44,46.9 L10.1
PVIN: length 18.2
  TOP w0.2: R50.1 4.01,73.94 4.27,74.19 5.54,74.19 5.57,74.22 U11.3 6.11,78.01 6.5,78.4 J11.1 13.95,78.4 14.7,79.15 C72.1 16,79.75 C73.1
VBUS: length 91.4
  TOP w0.127: J9.1 46.43,81.31 45.8,81.94 41.73,81.94 41.35,81.56 C74.1
  TOP w0.2: J9.1 47.65,77.75 58.95,77.75 59.1,77.9 ; v1(53.36,23.83) 53.36,23 53.25,22.89 53.25,12.45 53.41,12.28 D2.1 ; 59.1,77.9 L11.2 ; 59.1,77.9 v1(58.15,77.9)
  BOTTOM w0.127: 52.83,72.59 52.83,72.58
  BOTTOM w0.2: 52.83,72.59 52.84,72.59 v1(58.15,77.9) ; 52.83,72.58 52.83,25.07 53.36,24.54 v1(53.36,23.83)
ADC_MID: length 1.6
  TOP w0.127: C1.1 28.46,40.28 28.8,39.94 U1.96
AHS: length 6.8
  TOP w0.127: v1(46.43,27.71) C6.1
  TOP w0.2: U1.39 46.51,27.72 C6.1
  BOTTOM w0.127: v1(46.54,26.19) 46.54,26.21 46.43,26.32 v1(46.43,27.71) 46.54,27.82 46.54,28.33 v1(47.19,28.98)
BL_5V: length 9.6
  TOP w0.127: U4.6 55.86,49.99 55.76,50.09 L3.1 ; L12.2 51.38,52.18
  TOP w0.2: L3.1 55.45,51.39 55.45,52.22 55.32,52.35 51.56,52.35 51.38,52.18 C33.1
BL_ADJ: length 66.4
  TOP w0.127: U1.125 25.68,26.52 23.82,24.66 v1(21.41,24.66) ; 57.45,46.6 R22.1 ; 39.19,45.49 v1(39.32,45.49) ; v1(31.32,45.49) 30.55,46.25 23.7,46.25 22.55,45.11 v1(21.66,45.11)
  TOP w0.2: v1(39.32,45.49) 56.91,45.49 57.67,46.25 R22.1 ; U4.4 57.22,46.83 57.45,46.6
  BOTTOM w0.2: v1(21.41,24.66) 21.41,44.4 21.66,44.65 v1(21.66,45.11) ; v1(31.32,45.49) v1(39.32,45.49)
DEBUG_RX: length 27.4
  TOP w0.127: U1.105 26.23,34.52 25.81,34.94 20.73,34.94
  TOP w0.2: 20.73,34.94 18.01,34.94 13.3,39.65 J6.2
DEBUG_TX: length 28.3
  TOP w0.127: 20.7,35.4 20.9,35.2 25.95,35.2 26.23,34.92 U1.104
  TOP w0.2: J6.1 11.46,42.19 17.32,36.33 19.77,36.33 20.7,35.4
ETH_CRS: length 15.7
  TOP w0.127: v1(32.33,51.84) 33.1,51.08 33.1,40.9 33.2,40.8 U1.85
  BOTTOM w0.127: 32.78,53.77 31.97,53.77 31.82,53.62 31.82,52.35 v1(32.33,51.84)
ETH_INT: length 27.9
  TOP w0.127: 45.04,47.5 v1(45.04,46.26) ; 42.75,54 41.97,54 R36.1
  TOP w0.2: U1.52 45.03,32.92 v1(45.8,32.16) ; 42.75,54 43.13,54 45.03,52.1 45.03,47.51 45.04,47.5
  BOTTOM w0.2: v1(45.04,46.26) 45.8,45.5 v1(45.8,32.16)
ETH_INT_PU: length 5.1
  TOP w0.127: v1(38.67,55.77) 41.34,55.77 R43.1 41.46,55.29 41.6,55.14 41.62,55.14 41.77,54.99 41.77,54.92 42.18,54.51 R36.2
  BOTTOM w0.127: U7.11 v1(38.67,55.77)
ETH_LED0+: length 3.2
  TOP w0.127: R48.1 41.26,84.84 ; 41.26,84.84 41.24,84.87 J8.9 ; 41.26,84.84 41.35,84.75
ETH_LED0-: length 47.9
  TOP w0.127: 23.94,54.55 23.94,52.49 24.01,52.42 24.77,52.42 ; R47.1 24.59,52.6 24.77,52.42 ; 24.77,52.42 v1(33.03,52.42)
  TOP w0.2: J8.10 23.94,73.01 23.94,54.55
  BOTTOM w0.127: U7.24 v1(33.03,52.42)
ETH_LED1+: length 3.3
  TOP w0.127: R46.1 22.27,84.84 22.3,84.87 ; 22.3,84.87 J8.12 ; 22.3,84.87 22.16,84.87 22.05,84.75
ETH_LED1-: length 44.6
  TOP w0.127: R45.1 25.84,52.98 v1(25.98,52.98) v1(32.33,52.98)
  TOP w0.2: J8.11 28.9,83.57 28.9,79.41 23.44,73.95 v1(23.44,52.98)
  BOTTOM w0.127: v1(23.44,52.98) v1(25.98,52.98) ; 32.78,53.27 32.62,53.27 v1(32.33,52.98)
ETH_MDC: length 17.2
  TOP w0.127: U1.74 37.6,40.47 38.17,41.05 38.17,41.62 37.67,42.12 37.67,44.48 v1(37.41,44.73) ; 34.11,44.6 v1(34.24,44.73) 34.37,44.86 34.37,49.81 34.63,50.08 v1(34.63,50.58)
  BOTTOM w0.127: U7.22 v1(34.63,50.58) ; v1(37.41,44.73) 37.54,44.73
  BOTTOM w0.2: v1(34.24,44.73) 34.33,44.73 34.5,44.9 37.24,44.9 v1(37.41,44.73)
ETH_MDIO: length 29
  TOP w0.127: v1(37.03,50.19) 36.14,49.3 36.14,43.71 36.4,43.46 36.4,40.81 36,40.41 U1.78 ; 39.66,59.55 34.11,54 v1(34.11,51.46)
  TOP w0.2: 39.66,59.55 41.29,59.55 R44.1
  BOTTOM w0.2: U7.23 34.13,51.48 v1(34.11,51.46) 34.11,51.36 33.95,51.2 33.95,50.35 34.25,50.05 36.7,50.05 36.84,50.19 v1(37.03,50.19)
ETH_REFCLK: length 17
  TOP w0.127: v1(39.68,53.77) 39.68,53.64 39.7,53.62 39.7,53.24 38,51.54 38,42.15 38.43,41.72 38.43,40.79 38,40.36 U1.73
  BOTTOM w0.2: 37.98,53.77 v1(39.68,53.77)
ETH_RESET: length 101.9
  TOP w0.127: v1(46.94,31.9) 46.68,31.65 44.78,31.65 43.91,32.52 U1.51 ; v1(38.94,6.76) 39.46,6.24 J3.6 ; 67.44,51.37 67.44,51.34 67.39,51.29
  TOP w0.2: v1(51.64,58.7) 61.42,58.7 66.63,53.49 66.63,53.42 67.36,52.68 SW2.4 67.44,51.37 67.39,51.33 67.39,50.85 R7.1 67.35,50.81 C16.1 Q1.3 ; v1(46.94,31.9) v1(50.62,31.9) ; v1(45.92,46.25) v1(45.92,58.7) R37.1 ; v1(50.49,23.77) 50.49,17.55 v1(43,10.06)
  BOTTOM w0.2: v1(46.94,31.9) 46.15,32.69 46.15,45.9 45.92,46.13 v1(45.92,46.25) ; v1(50.62,31.9) 50.62,23.9 v1(50.49,23.77) ; v1(51.64,58.7) v1(45.92,58.7) ; v1(43,10.06) 40.72,10.06 38.94,8.28 v1(38.94,6.76)
ETH_RXD0: length 28.1
  TOP w0.127: U1.86 32.8,40.05
  TOP w0.2: 32.8,40.05 32.8,48.71 v1(32.33,49.17)
  BOTTOM w0.2: U7.9 38.11,56.9 39.6,56.9 40.73,55.77 40.73,49.83 39.65,48.75 32.76,48.75 v1(32.33,49.17)
ETH_RXD1: length 28.2
  TOP w0.2: v1(32.08,50.32) 31.55,49.79 31.55,48.75 32.4,47.9 U1.87
  BOTTOM w0.2: U7.10 38.47,56.27 38.61,56.41 39.34,56.41 40.1,55.65 40.1,55.63 40.36,55.37 40.36,50.36 40.22,50.22 40.21,50.22 39.56,49.57 39.56,49.54 32.86,49.54 v1(32.08,50.32)
ETH_RXDV: length 2.4
  BOTTOM w0.2: v1(37.79,59.72) 37.13,59.05 U7.8
ETH_RXER: length 23.7
  TOP w0.127: U1.88 32,40.05 ; R49.2 36.91,57.89 33.27,54.26 v1(31.7,54.26)
  TOP w0.2: v1(31.57,51.84) 31,51.27 31,48.6 32,47.6 32,40.05
  BOTTOM w0.127: U7.28 32.08,54.77 31.57,54.26 ; v1(31.57,51.84) 31.57,54.26 ; 31.57,54.26 v1(31.7,54.26)
ETH_TXD0: length 15.2
  TOP w0.127: U1.79 35.6,40.5 36.14,41.05 36.14,43.33 35.76,43.71 35.76,49.68 38.17,52.1 v1(38.17,52.86)
  BOTTOM w0.127: 37.98,53.27 38.17,53.07 v1(38.17,52.86)
ETH_TXD1: length 14.5
  TOP w0.127: U1.80 35.2,40.61 35.89,41.3 35.89,43.21 35.51,43.59 35.51,49.79 37.54,51.82 v1(37.54,52.35)
  BOTTOM w0.2: U7.17 37.2,52.35 v1(37.54,52.35)
ETH_TXEN: length 14.1
  TOP w0.127: v1(36.14,51.46) 36.14,50.83 35.64,50.32 35.63,50.32 35.63,50.31 35.13,49.81 35.13,43.59 35.63,43.08 35.63,41.43 34.8,40.59 U1.81
  BOTTOM w0.2: U7.20 35.63,51.97 v1(36.14,51.46)
ETH_VCCD: length 97.4
  TOP w0.127: R48.2 41.12,85.88 22.3,85.88 22.06,85.64 R46.2 ; L5.2 46.6,60.72 46.59,60.73 v1(42.75,60.73) C54.1 ; C54.1 42.28,61.2 42.24,61.24 42.24,61.24 42.02,61.46 RN2.5 RN2.6 RN2.7 RN2.8 ; C54.1 42.28,60.27 42.26,60.25 42.26,60.21 42.23,60.18 42.23,59.74 R44.2 ; 35.05,60.61 26.74,60.61 25.6,59.46 R45.2 25.58,53.99 24.61,53.99 R47.2 ; v1(40.59,73.81) R35.2 ; v1(43.38,56.41) C51.1 42.92,56.76 42.83,56.67 R38.1 42.23,56.64 42.23,55.68 R43.2
  TOP w0.2: 36.78,60.63 36.78,59.72 v1(36.91,59.59) ; 36.78,60.63 36.9,60.75 39.95,60.75 40.63,61.43 RN2.5 ; 36.78,60.63 36.76,60.61 35.05,60.61 ; RN2.8 v1(40.63,63.74) ; v1(41.35,86) R48.2
  BOTTOM w0.2: v1(41.35,86) 40.63,85.28 ; 40.63,85.28 40.59,85.24 v1(40.59,73.81) ; 40.63,85.28 v1(40.63,63.74) ; v1(36.91,59.59) 36.91,59.38 36.63,59.11 ; 36.63,59.11 36.66,59.11 ; 36.63,59.11 36.63,57.62 ; v1(42.75,60.73) 43.38,60.1 v1(43.38,56.41)
GPG7: length 22
  TOP w0.2: v1(45.29,27.08) 44.76,27.08 44.51,27.32 U1.38
  BOTTOM w0.2: v1(45.29,27.08) 45.29,31.71 45.15,31.85 45.15,45.3 44.19,46.25 R31.1
HPOUTL: length 16.9
  TOP w0.127: U1.102 26.31,35.72 25.26,36.77 20.55,36.77
  TOP w0.2: 20.55,36.77 17.63,36.77 13.41,40.99 v1(13.41,41.3)
  BOTTOM w0.2: C40.1 13.41,42.02 v1(13.41,41.3)
HPOUTR: length 29.6
  TOP w0.127: U1.101 26.31,36.12 25.34,37.1 18.12,37.1
  TOP w0.2: v1(14.43,41.3) 14.43,40.77 18.1,37.1 18.12,37.1
  BOTTOM w0.2: C41.2 14.05,55.02 14.43,54.64 v1(14.43,41.3)
ISI_HSYNC: length 20.7
  TOP w0.127: 36.78,12.6 36.78,12.47 36.8,12.45 36.8,12.89 36.79,12.9 36.79,13.31 36.8,13.32 U1.21 ; v1(36.78,10.57) 37.03,10.31 37.03,7.01 37.96,6.09 J3.9
  TOP w0.2: v1(37.54,11.71) 36.8,12.45
  BOTTOM w0.2: v1(36.78,10.57) 36.78,11.1 37.03,11.35 37.05,11.35 37.41,11.71 v1(37.54,11.71)
ISI_PCLK: length 18.7
  TOP w0.127: v1(34.49,13.11) 34.37,13.11 33.73,12.47 33.73,12.25 ; 33.73,11.8 33.73,11.05
  TOP w0.2: 33.73,11.05 R16.1 ; 33.73,12.25 33.73,11.8 ; 37.15,13.55 37.29,13.41 v1(37.29,13.11) 37.2,13.19 U1.22
  BOTTOM w0.2: v1(34.49,13.11) v1(37.29,13.11)
ISI_PWDN: length 20.4
  TOP w0.127: 36,12.11 37.29,10.82 37.29,7.16 38.46,5.99 J3.8
  TOP w0.2: U1.19 36,12.11
ISI_SCL: length 42.6
  TOP w0.127: R19.2 39.66,7.8 39.66,7.28 39.96,6.99 J3.5 ; v1(52.02,30.12) 50.88,30.12 50.37,30.63 43.98,30.63 43.69,30.92 U1.47
  TOP w0.2: v1(52.27,23.77) 52.27,17.55 v1(42.62,7.9)
  BOTTOM w0.2: v1(42.62,7.9) v1(39.57,7.9) ; v1(52.27,23.77) 52.27,24.05 52.02,24.3 v1(52.02,30.12)
ISI_SCLK: length 20.6
  TOP w0.127: 35.38,10.1 35.38,8.94 R15.1 ; 38.81,12.22 v1(38.81,12.34)
  TOP w0.2: U1.23 37.6,15.08 38.81,13.87 v1(38.81,12.34) ; 35.38,10.1 35.38,11.33 v1(34.37,12.34)
  BOTTOM w0.2: v1(34.37,12.34) v1(38.81,12.34)
ISI_SDA: length 42.3
  TOP w0.127: J3.3 40.96,9.18 40.72,9.42 ; U1.48 43.71,31.32 44.14,30.89 50.51,30.89 50.76,30.63 v1(51.26,30.63)
  TOP w0.2: R20.2 43.45,9.42 51.26,17.23 v1(51.26,23.77)
  BOTTOM w0.127: 51.26,30.89 v1(51.26,30.63)
  BOTTOM w0.2: v1(51.26,23.77) v1(51.26,30.63)
ISI_VSYNC: length 20.4
  TOP w0.127: J3.7 38.96,5.85 37.54,7.27 37.54,10.95 36.4,12.09 36.4,12.3
  TOP w0.2: 36.4,12.3 36.4,12.3 U1.20
LED+: length 14.4
  TOP w0.127: U4.5 57.57,47.78 C34.1 58.22,47.74 58.28,47.79 D1.1
  TOP w0.2: v1(61.42,42.95) 61.95,42.95 62.05,43.06 J2.2 ; v1(61.16,47.52) 60.89,47.79 D1.1
  BOTTOM w0.2: v1(61.42,42.95) 61.16,43.21 v1(61.16,47.52)
LED-: length 16.4
  TOP w0.2: v1(54.18,46.38) 53.73,46.83 U4.3 52.43,46.83 52.4,46.8 51.48,46.8 51.38,46.7 ; J2.1 55.73,43.56 v1(54.43,44.86)
  BOTTOM w0.2: v1(54.18,46.38) 54.18,45.11 v1(54.43,44.86)
LHSYNC: length 45.4
  TOP w0.127: 54.94,27.97 v1(54.81,28.09) 59.13,28.09 v1(59.26,27.97) ; 62.8,28.06 v1(61.51,28.06) ; v1(37.67,41.3) 37.67,40.92 37.2,40.45 U1.75
  TOP w0.2: v1(38.56,42.32) v1(54.43,42.32) ; J2.32 62.8,28.06
  BOTTOM w0.2: v1(38.56,42.32) 38.58,42.3 38.58,41.67 38.2,41.3 v1(37.67,41.3) ; v1(54.43,42.32) 54.43,42.23 54.25,42.05 54.25,28.66 v1(54.81,28.09) ; v1(61.51,28.06) 61.2,27.75 59.5,27.75 59.28,27.97 v1(59.26,27.97)
LPCLK: length 45.1
  TOP w0.127: v1(37.16,43.08) 37.16,40.79 36.8,40.43 U1.76
  TOP w0.2: J2.30 63.95,29.06 63.64,29.36 v1(62.18,29.36) ; v1(38.56,43.08) 39.15,43.08 39.28,42.95 40.1,42.95 40.25,43.1 60.25,43.1 60.53,42.82 v1(60.53,42.7)
  BOTTOM w0.2: v1(60.53,42.7) 62.18,41.05 v1(62.18,29.36) ; v1(37.16,43.08) v1(38.56,43.08)
LRADC: length 37.3
  TOP w0.127: 59.1,26.06 59.26,26.06 v1(59.38,26.19) ; 45.8,28.47 45.44,28.12 44.87,28.12 44.86,28.11 44.45,28.11 44.43,28.12 U1.40 ; 59.38,22.76 v1(59.38,24.28)
  TOP w0.2: SW3.4 67.12,15.4 64.88,13.15 64.1,13.15 R25.1 63.9,15.75 62.01,17.64 C39.1 62.01,20.57 R23.1 61.54,20.6 59.38,22.76 ; 59.1,26.06 55.95,26.06 53.54,28.47 47.44,28.47 47.41,28.45 46.97,28.45 46.95,28.47 45.8,28.47
  BOTTOM w0.2: v1(59.38,26.19) v1(59.38,24.28)
LVD0: length 23
  TOP w0.127: 62.1,32.55 59.75,32.55
  TOP w0.2: J2.23 62.11,32.56 62.1,32.55 ; U1.53 53.15,33.32 53.92,32.55 59.75,32.55
LVD1: length 25.5
  TOP w0.2: U1.54 54.14,33.72 54.56,33.3 54.56,33.29 54.7,33.15 56.44,33.15 v1(56.59,33.3) ; J2.24 59.97,32.06 59.05,31.14 v1(56.59,31.14)
  BOTTOM w0.2: v1(56.59,33.3) v1(56.59,31.14)
LVD2: length 26.2
  TOP w0.127: v1(55.45,30.63) 59.45,30.63
  TOP w0.2: 59.45,30.63 60.55,31.73 63.02,31.73 63.19,31.56 J2.25 ; v1(54.94,33.81) 54.62,34.12 U1.55
  BOTTOM w0.2: v1(55.45,30.63) 55.45,33.3 v1(54.94,33.81)
LVD3: length 25.6
  TOP w0.127: v1(62.81,33.17) 62.18,33.17 61.81,32.8 60.39,32.8 60.19,33 60.08,33.11 57.67,33.11 56.97,33.81 55.7,33.81 54.99,34.52
  TOP w0.2: J2.26 v1(62.81,31.06) ; U1.56 54.99,34.52
  BOTTOM w0.2: v1(62.81,33.17) v1(62.81,31.06)
LVD4: length 26.2
  TOP w0.127: v1(60.65,33.3) 60.53,33.43 57.73,33.43 56.97,34.19 55.9,34.19 55.88,34.2 55.88,34.2 55.59,34.49 55.59,34.5 55.34,34.74 ; 62.5,30.51 63.15,30.51
  TOP w0.2: 63.15,30.51 63.2,30.56 J2.27 ; v1(60.65,30.63) 61.15,30.63 61.28,30.51 62.5,30.51 ; 55.34,34.74 55.16,34.92 U1.57
  BOTTOM w0.127: 60.65,30.51 v1(60.65,30.63)
  BOTTOM w0.2: v1(60.65,33.3) v1(60.65,30.63)
LVD5: length 27.8
  TOP w0.127: 55.58,35.32 55.95,34.95 55.95,34.82 v1(56.08,34.7)
  TOP w0.2: U1.58 55.58,35.32 ; J2.28 v1(56.28,30.06)
  BOTTOM w0.18: v1(56.28,30.06) 56.15,30.18 56.15,30.8 56,30.95 56,31.45
  BOTTOM w0.2: v1(56.08,34.7) 56.08,34.53 55.8,34.25 55.8,31.65 56,31.45
LVD6: length 27.2
  TOP w0.127: v1(61.42,33.43) 61.03,33.81 57.73,33.81 56.17,35.37
  TOP w0.2: 56.17,35.37 55.82,35.72 U1.59 ; v1(61.42,36.86) 61.71,36.56 J2.15
  BOTTOM w0.2: v1(61.42,36.86) v1(61.42,33.43)
LVD7: length 22.9
  TOP w0.127: 55.85,36.12 59.67,36.12 59.89,36.35 v1(60.78,36.35)
  TOP w0.2: J2.16 61.24,36.06 60.95,36.35 v1(60.78,36.35) ; U1.60 55.85,36.12
LVD8: length 24.7
  TOP w0.2: J2.17 60.43,35.56 v1(60.27,35.71) ; v1(60.27,37.24) 59.56,36.52 U1.61
  BOTTOM w0.2: v1(60.27,35.71) 60.1,35.89 60.1,37 60.27,37.17 v1(60.27,37.24)
LVD9: length 25.6
  TOP w0.2: J2.18 59.78,35.06 v1(59.64,35.2) ; U1.62 58.81,36.92 v1(59.64,37.74)
  BOTTOM w0.2: v1(59.64,37.74) v1(59.64,35.2)
LVD10: length 26.5
  TOP w0.2: U1.63 57.95,37.32 v1(58.81,38.19) ; v1(59,34.7) 59.14,34.56 J2.19
  BOTTOM w0.2: v1(59,34.7) 59,34.81 58.81,35 v1(58.81,38.19)
LVD11: length 30.5
  TOP w0.127: 61.55,34.06 61.14,34.06 61.14,34.06 58.24,34.06 v1(56.97,35.33) ; U1.66 40.8,40.12 40.97,40.28 56.08,40.28 v1(56.34,40.03)
  TOP w0.2: J2.20 61.55,34.06
  BOTTOM w0.2: v1(56.34,40.03) 56.34,35.97 v1(56.97,35.33)
LVD12: length 26.1
  TOP w0.127: U1.67 40.4,40.21 40.73,40.54 57.08,40.54 57.09,40.55 57.43,40.55 57.44,40.56 J2.7
LVD13: length 28.1
  TOP w0.127: v1(57.1,39.9) 57.1,39.93 57.23,40.06 J2.8 ; v1(57.23,41.05) 56.97,40.79 40.58,40.79 40,40.21 U1.68
  BOTTOM w0.127: 57.14,40.46 57.1,40.42
  BOTTOM w0.2: 57.1,40.42 v1(57.1,39.9) ; v1(57.23,41.05) 57.23,40.55 57.14,40.46
LVD14: length 29.8
  TOP w0.127: U1.69 39.6,40.21 40.43,41.05 55.7,41.05 55.9,41.25 55.9,41.25 ; J2.9 v1(57.96,39.56)
  TOP w0.2: v1(58.11,41.3) 58.05,41.3 57.7,41.65 56.3,41.65 55.9,41.25
  BOTTOM w0.127: 58.09,41.05 58.11,41.05 58.11,41.08
  BOTTOM w0.2: v1(57.96,39.56) 57.96,41.14 v1(58.11,41.3) 58.11,41.08 58.09,41.05
LVD15: length 31.1
  TOP w0.127: J2.10 58.79,39.06 v1(58.75,39.02) ; U1.70 39.2,40.29 40.21,41.3 55.32,41.3 55.55,41.53 55.55,41.55
  TOP w0.2: v1(59,41.17) 59,41.55 58.55,42 56,42 55.55,41.55
  BOTTOM w0.2: v1(58.75,39.02) 58.75,40.79 59,41.05 v1(59,41.17)
LVD16: length 32.2
  TOP w0.127: J2.11 v1(59.64,38.56) ; U1.71 38.8,40.27 40.08,41.55 55.05,41.55 55.3,41.8 55.3,41.8
  TOP w0.2: v1(59.77,41.17) 59.75,41.19 59.75,41.85 59.2,42.4 55.9,42.4 55.3,41.8
  BOTTOM w0.2: v1(59.77,41.17) 59.77,38.68 v1(59.64,38.56)
